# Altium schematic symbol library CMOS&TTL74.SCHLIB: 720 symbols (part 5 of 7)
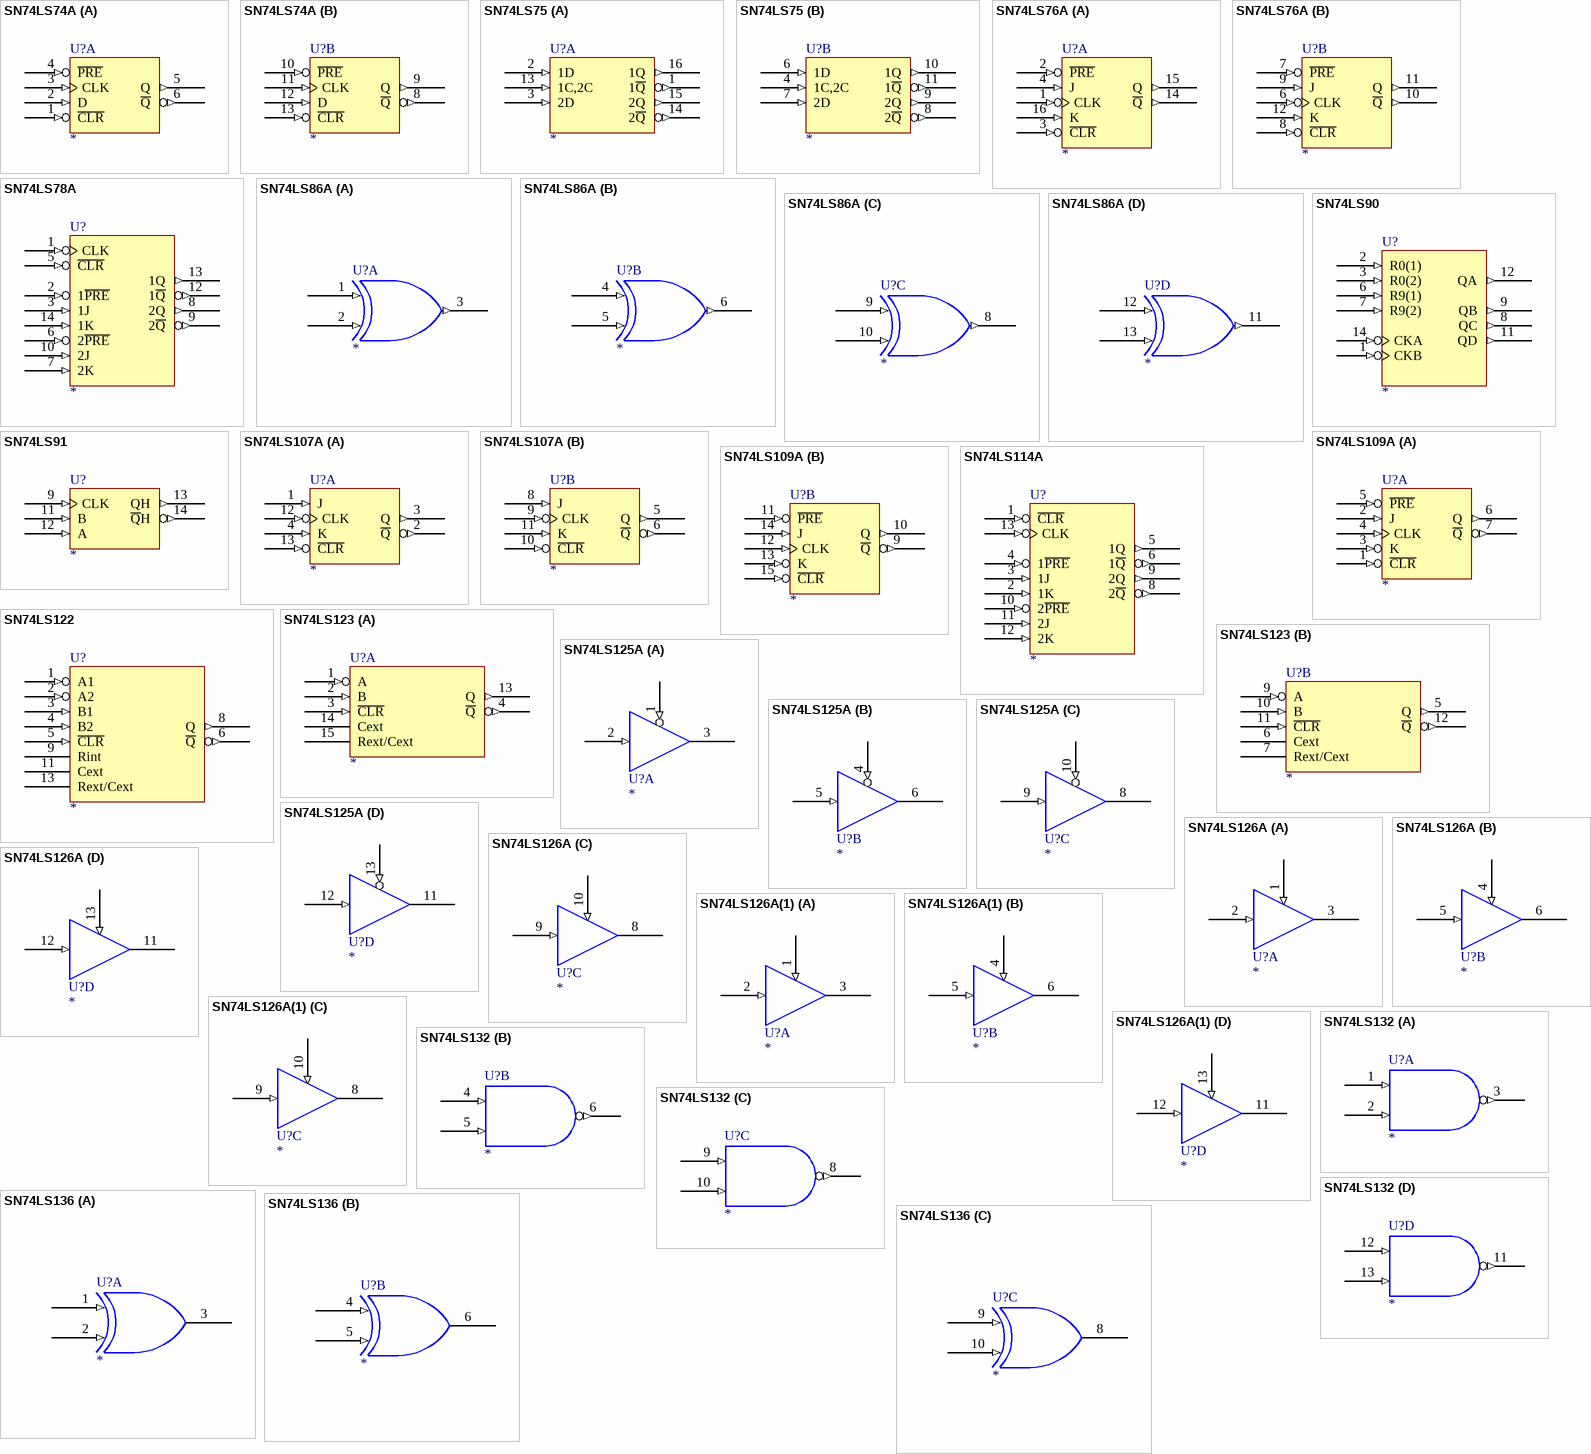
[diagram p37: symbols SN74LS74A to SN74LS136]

## SN74LS86A
designator U?
QUAD 2-IN XOR  G
footprint SO14
footprint DIP-14
part A pins: 1 (in), 2 (in), 3 (out), 7 GND (power) hidden to GND, 14 VCC (power) hidden to VCC
part B pins: 4 (in), 5 (in), 6 (out), 7 GND (power) hidden to GND, 14 VCC (power) hidden to VCC
part C pins: 7 GND (power) hidden to GND, 8 (out), 9 (in), 10 (in), 14 VCC (power) hidden to VCC
part D pins: 7 GND (power) hidden to GND, 11 (out), 12 (in), 13 (in), 14 VCC (power) hidden to VCC
1 alternate drawing of the same symbol

## SN74LS90
designator U?
DECADE DIV-BY-12 BIN CNT
footprint SO14
footprint DIP-14
pins: 1 CKB (in), 2 R0(1) (in), 3 R0(2) (in), 5 VCC (power) hidden to VCC, 6 R9(1) (in), 7 R9(2) (in), 8 QC (out), 9 QB (out), 10 GND (power) hidden to GND, 11 QD (out), 12 QA (out), 14 CKA (in)
1 alternate drawing of the same symbol

## SN74LS91
designator U?
8-BIT SHIFT REG
footprint SO14
footprint DIP-14
pins: 5 VCC (power) hidden to VCC, 9 CLK (in), 10 GND (power) hidden to GND, 11 B (in), 12 A (in), 13 QH (out), 14 ~{Q}H (out)
1 alternate drawing of the same symbol

## SN74LS107A
designator U?
DUAL J-K FF CR
footprint SO14
footprint DIP-14
part A pins: 1 J (in), 2 ~{Q} (out), 3 Q (out), 4 K (in), 7 GND (power) hidden to GND, 12 CLK (in), 13 ~{CLR} (in), 14 VCC (power) hidden to VCC
part B pins: 5 Q (out), 6 ~{Q} (out), 7 GND (power) hidden to GND, 8 J (in), 9 CLK (in), 10 ~{CLR} (in), 11 K (in), 14 VCC (power) hidden to VCC
1 alternate drawing of the same symbol

## SN74LS109A
designator U?
DUAL J-K PET FF RS CR
footprint SO16
footprint DIP-16
part A pins: 1 ~{CLR} (in), 2 J (in), 3 K (in), 4 CLK (in), 5 ~{PRE} (in), 6 Q (out), 7 ~{Q} (out), 8 GND (power) hidden to GND, 16 VCC (power) hidden to VCC
part B pins: 8 GND (power) hidden to GND, 9 ~{Q} (out), 10 Q (out), 11 ~{PRE} (in), 12 CLK (in), 13 K (in), 14 J (in), 15 ~{CLR} (in), 16 VCC (power) hidden to VCC
1 alternate drawing of the same symbol

## SN74LS114A
designator U?
DUAL J-K NET FF RS COM CR COM CLK
footprint SO14
footprint DIP-14
pins: 1 ~{CLR} (in), 2 1K (in), 3 1J (in), 4 1~{PRE} (in), 5 1Q (out), 6 1~{Q} (out), 7 GND (power) hidden to GND, 8 2~{Q} (out), 9 2Q (out), 10 2~{PRE} (in), 11 2J (in), 12 2K (in), 13 CLK (in), 14 VCC (power) hidden to VCC
1 alternate drawing of the same symbol

## SN74LS122
designator U?
RETRIGGERABLE MONOSTABLE MULTIVIBRATOR
footprint SO14
footprint DIP-14
pins: 1 A1 (in), 2 A2 (in), 3 B1 (in), 4 B2 (in), 5 ~{CLR} (in), 6 ~{Q} (out), 7 GND (power) hidden to GND, 8 Q (out), 9 Rint, 11 Cext, 13 Rext/Cext, 14 VCC (power) hidden to VCC
1 alternate drawing of the same symbol

## SN74LS123
designator U?
RETRIGGERABLE MONOSTABLE MULTIVIBRATOR
footprint SO16
footprint DIP-16
part A pins: 1 A (in), 2 B (in), 3 ~{CLR} (in), 4 ~{Q} (out), 8 GND (power) hidden to GND, 13 Q (out), 14 Cext, 15 Rext/Cext, 16 VCC (power) hidden to VCC
part B pins: 5 Q (out), 6 Cext, 7 Rext/Cext, 8 GND (power) hidden to GND, 9 A (in), 10 B (in), 11 ~{CLR} (in), 12 ~{Q} (out), 16 VCC (power) hidden to VCC
1 alternate drawing of the same symbol

## SN74LS125A
designator U?
QUAD BUS BUF 3SO
footprint SO14
footprint DIP-14
part A pins: 1 (in), 2 (in), 3 (hiz), 7 GND (power) hidden to GND, 14 VCC (power) hidden to VCC
part B pins: 4 (in), 5 (in), 6 (hiz), 7 GND (power) hidden to GND, 14 VCC (power) hidden to VCC
part C pins: 7 GND (power) hidden to GND, 8 (hiz), 9 (in), 10 (in), 14 VCC (power) hidden to VCC
part D pins: 7 GND (power) hidden to GND, 11 (hiz), 12 (in), 13 (in), 14 VCC (power) hidden to VCC
2 alternate drawings of the same symbol

## SN74LS126A
designator U?
QUAD BUS BUF 3SO
footprint SO14
footprint DIP-14
part A pins: 1 (in), 2 (in), 3 (hiz), 7 GND (power) hidden to GND, 14 VCC (power) hidden to VCC
part B pins: 4 (in), 5 (in), 6 (hiz), 7 GND (power) hidden to GND, 14 VCC (power) hidden to VCC
part C pins: 7 GND (power) hidden to GND, 8 (hiz), 9 (in), 10 (in), 14 VCC (power) hidden to VCC
part D pins: 7 GND (power) hidden to GND, 11 (hiz), 12 (in), 13 (in), 14 VCC (power) hidden to VCC
2 alternate drawings of the same symbol

## SN74LS126A(1)
designator U?
QUAD BUS BUF 3SO
footprint DIP-14
part A pins: 1 (in), 2 (in), 3 (hiz), 7 GND (power) hidden to GND, 14 VCC (power) hidden to VCC
part B pins: 4 (in), 5 (in), 6 (hiz), 7 GND (power) hidden to GND, 14 VCC (power) hidden to VCC
part C pins: 7 GND (power) hidden to GND, 8 (hiz), 9 (in), 10 (in), 14 VCC (power) hidden to VCC
part D pins: 7 GND (power) hidden to GND, 11 (hiz), 12 (in), 13 (in), 14 VCC (power) hidden to VCC
2 alternate drawings of the same symbol

## SN74LS132
designator U?
QUAD 2-IN POS NAND SCH
footprint SO14
footprint DIP-14
part A pins: 1 (in), 2 (in), 3 (out), 7 GND (power) hidden to GND, 14 VCC (power) hidden to VCC
part B pins: 4 (in), 5 (in), 6 (out), 7 GND (power) hidden to GND, 14 VCC (power) hidden to VCC
part C pins: 7 GND (power) hidden to GND, 8 (out), 9 (in), 10 (in), 14 VCC (power) hidden to VCC
part D pins: 7 GND (power) hidden to GND, 11 (out), 12 (in), 13 (in), 14 VCC (power) hidden to VCC
2 alternate drawings of the same symbol

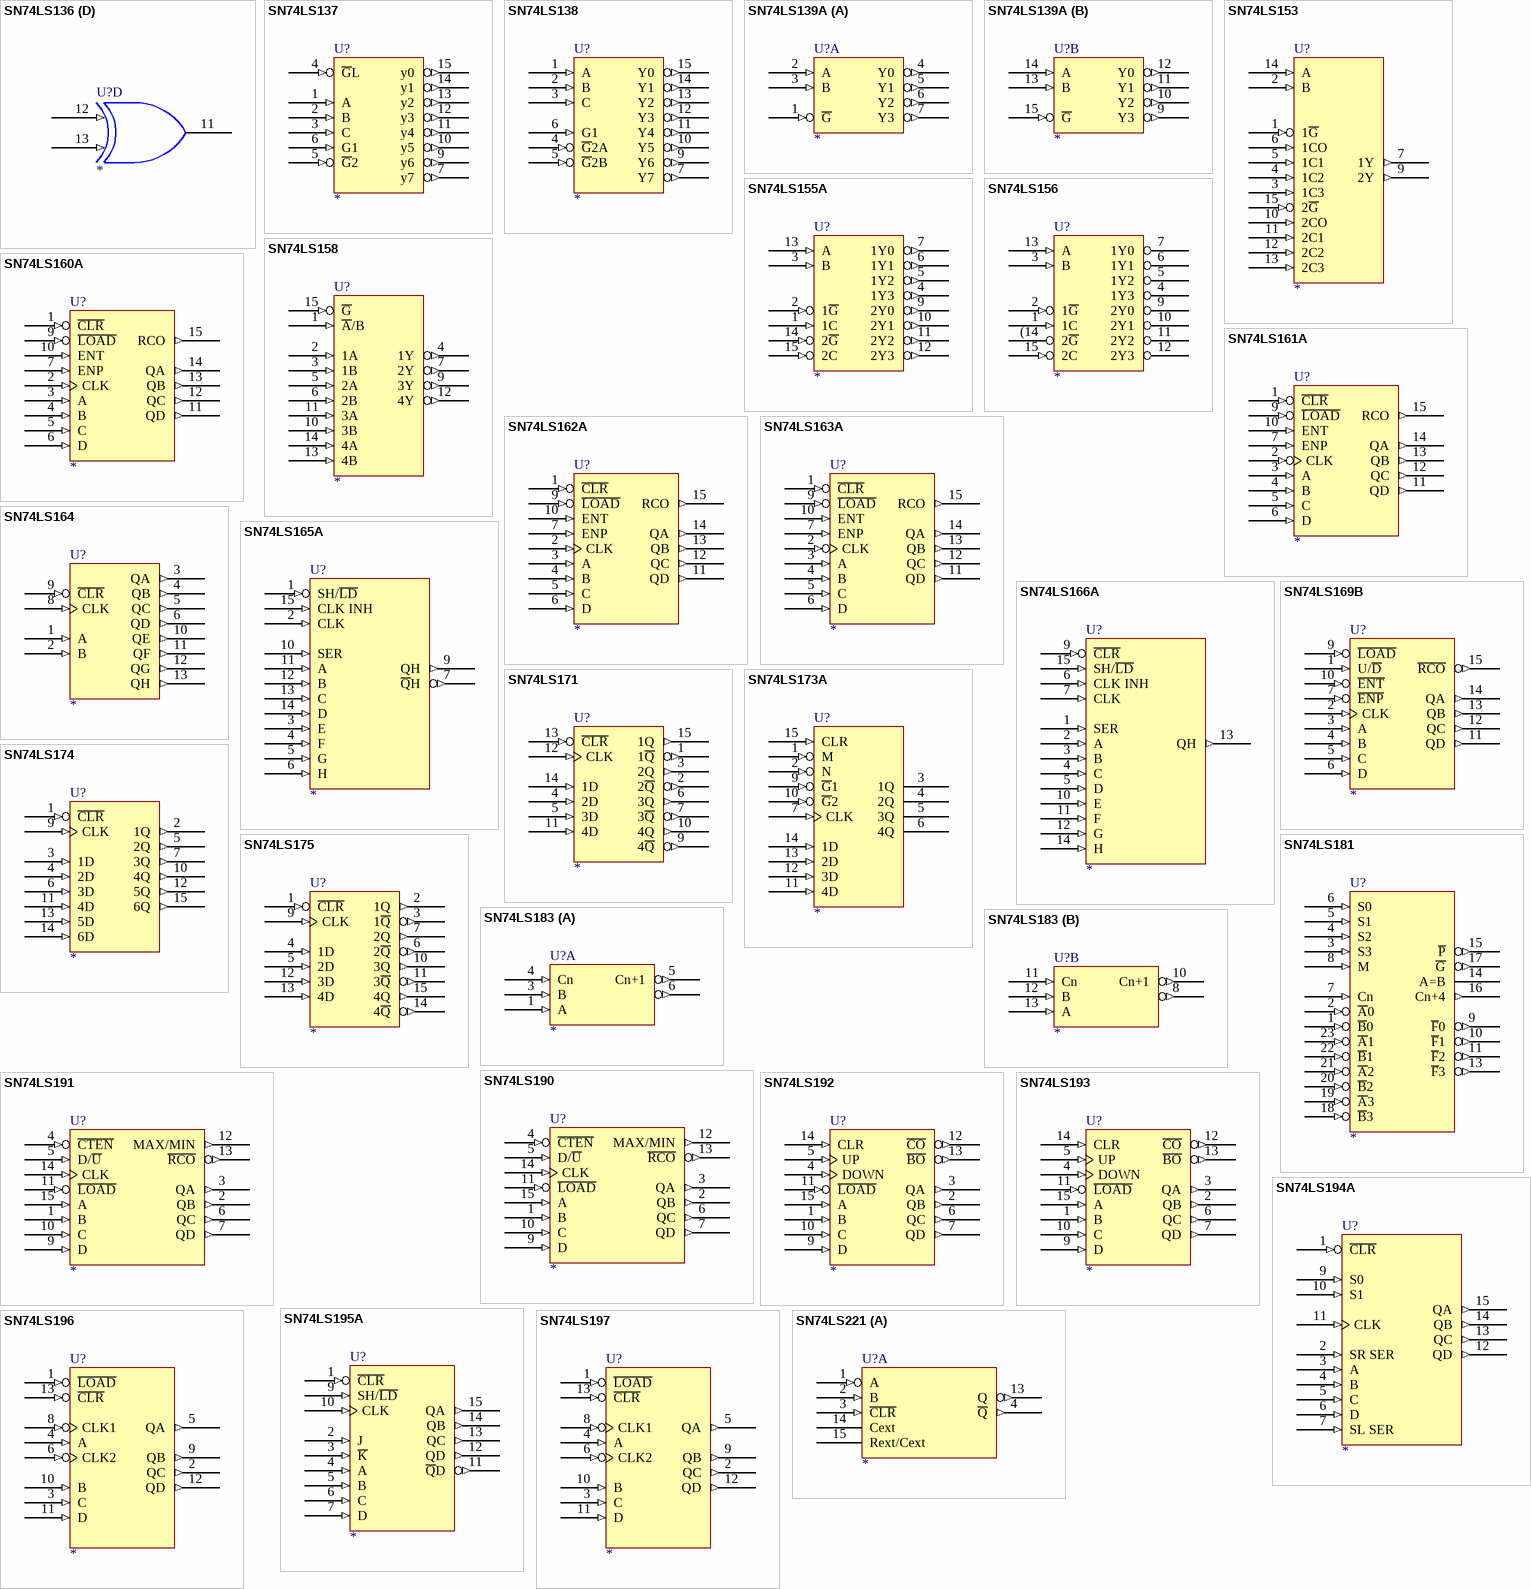
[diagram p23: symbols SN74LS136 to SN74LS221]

## SN74LS136
designator U?
QUAD 2-IN XOR  G OCO
footprint DIP-14
part A pins: 1 (in), 2 (in), 3 (oc), 7 GND (power) hidden to GND, 14 VCC (power) hidden to VCC
part B pins: 4 (in), 5 (in), 6 (oc), 7 GND (power) hidden to GND, 14 VCC (power) hidden to VCC
part C pins: 7 GND (power) hidden to GND, 8 (oc), 9 (in), 10 (in), 14 VCC (power) hidden to VCC
part D pins: 7 GND (power) hidden to GND, 11 (oc), 12 (in), 13 (in), 14 VCC (power) hidden to VCC
1 alternate drawing of the same symbol

## SN74LS137
designator U?
3-8LINE DEC/DEMUL ADDRESS LCH
footprint SO16
footprint DIP-16
pins: 1 A (in), 2 B (in), 3 C (in), 4 ~{G}L (in), 5 ~{G}2 (in), 6 G1 (in), 7 y7 (out), 8 GND (power) hidden to GND, 9 y6 (out), 10 y5 (out), 11 y4 (out), 12 y3 (out), 13 y2 (out), 14 y1 (out), 15 y0 (out), 16 VCC (power) hidden to VCC
1 alternate drawing of the same symbol

## SN74LS138
designator U?
3-8LINE DEC/DEMUL
footprint SO16
footprint DIP-16
pins: 1 A (in), 2 B (in), 3 C (in), 4 ~{G}2A (in), 5 ~{G}2B (in), 6 G1 (in), 7 Y7 (out), 8 GND (power) hidden to GND, 9 Y6 (out), 10 Y5 (out), 11 Y4 (out), 12 Y3 (out), 13 Y2 (out), 14 Y1 (out), 15 Y0 (out), 16 VCC (power) hidden to VCC
1 alternate drawing of the same symbol

## SN74LS139A
designator U?
DUAL 2-4LINE DEC/DEMULT
footprint SO16
footprint DIP-16
part A pins: 1 ~{G} (in), 2 A (in), 3 B (in), 4 Y0 (out), 5 Y1 (out), 6 Y2 (out), 7 Y3 (out), 8 GND (power) hidden to GND, 16 VCC (power) hidden to VCC
part B pins: 8 GND (power) hidden to GND, 9 Y3 (out), 10 Y2 (out), 11 Y1 (out), 12 Y0 (out), 13 B (in), 14 A (in), 15 ~{G} (in), 16 VCC (power) hidden to VCC
1 alternate drawing of the same symbol

## SN74LS153
designator U?
DUAL 4-1 LINE DATA SELEC/MUX
footprint SO16
footprint DIP-16
pins: 1 1~{G} (in), 2 B (in), 3 1C3 (in), 4 1C2 (in), 5 1C1 (in), 6 1CO (in), 7 1Y (out), 8 GND (power) hidden to GND, 9 2Y (out), 10 2CO (in), 11 2C1 (in), 12 2C2 (in), 13 2C3 (in), 14 A (in), 15 2~{G} (in), 16 VCC (power) hidden to VCC
1 alternate drawing of the same symbol

## SN74LS155A
designator U?
DUAL 2-4 LINE DEC/DEMUL
footprint SO16
footprint DIP-16
pins: 1 1C (in), 2 1~{G} (in), 3 B (in), 4 1Y3 (out), 5 1Y2 (out), 6 1Y1 (out), 7 1Y0 (out), 8 GND (power) hidden to GND, 9 2Y0 (out), 10 2Y1 (out), 11 2Y2 (out), 12 2Y3 (out), 13 A (in), 14 2~{G} (in), 15 2C (in), 16 VCC (power) hidden to VCC
1 alternate drawing of the same symbol

## SN74LS156
designator U?
DUAL 2-4 LINE DEC/DEMUL
footprint DIP-16
pins: 1 1C (in), 2 1~{G} (in), 3 B (in), 4 1Y3 (oc), 5 1Y2 (oc), 6 1Y1 (oc), 7 1Y0 (oc), 8 GND (power) hidden to GND, 9 2Y0 (oc), 10 2Y1 (oc), 11 2Y2 (oc), 12 2Y3 (oc), 13 A (in), 15 2C (in), 16 VCC (power) hidden to VCC, (14 2~{G}
1 alternate drawing of the same symbol

## SN74LS158
designator U?
QUAD 2-1LINE DATA SELEC/MUX
footprint SO16
footprint DIP-16
pins: 1 ~{A}/B (in), 2 1A (in), 3 1B (in), 4 1Y (out), 5 2A (in), 6 2B (in), 7 2Y (out), 8 GND (power) hidden to GND, 9 3Y (out), 10 3B (in), 11 3A (in), 12 4Y (out), 13 4B (in), 14 4A (in), 15 ~{G} (in), 16 VCC (power) hidden to VCC
1 alternate drawing of the same symbol

## SN74LS160A
designator U?
SYN 4-BIT CNT
footprint SO16
footprint DIP-16
pins: 1 ~{CLR} (in), 2 CLK (in), 3 A (in), 4 B (in), 5 C (in), 6 D (in), 7 ENP (in), 8 GND (power) hidden to GND, 9 ~{LOAD} (in), 10 ENT (in), 11 QD (out), 12 QC (out), 13 QB (out), 14 QA (out), 15 RCO (out), 16 VCC (power) hidden to VCC
1 alternate drawing of the same symbol

## SN74LS161A
designator U?
SYN 4-BIT CNT
footprint DIP-16
footprint SO16
pins: 1 ~{CLR} (in), 2 CLK (in), 3 A (in), 4 B (in), 5 C (in), 6 D (in), 7 ENP (in), 8 GND (power) hidden to GND, 9 ~{LOAD} (in), 10 ENT (in), 11 QD (out), 12 QC (out), 13 QB (out), 14 QA (out), 15 RCO (out), 16 VCC (power) hidden to VCC
1 alternate drawing of the same symbol

## SN74LS162A
designator U?
SYN 4-BIT CNT
footprint SO16
footprint DIP-16
pins: 1 ~{CLR} (in), 2 CLK (in), 3 A (in), 4 B (in), 5 C (in), 6 D (in), 7 ENP (in), 8 GND (power) hidden to GND, 9 ~{LOAD} (in), 10 ENT (in), 11 QD (out), 12 QC (out), 13 QB (out), 14 QA (out), 15 RCO (out), 16 VCC (power) hidden to VCC
1 alternate drawing of the same symbol

## SN74LS163A
designator U?
SYN 4-BIT CNT
footprint SO16
footprint DIP-16
pins: 1 ~{CLR} (in), 2 CLK (in), 3 A (in), 4 B (in), 5 C (in), 6 D (in), 7 ENP (in), 8 GND (power) hidden to GND, 9 ~{LOAD} (in), 10 ENT (in), 11 QD (out), 12 QC (out), 13 QB (out), 14 QA (out), 15 RCO (out), 16 VCC (power) hidden to VCC
1 alternate drawing of the same symbol

## SN74LS164
designator U?
8-BIT PALL SERI SFT REG
footprint SO14
footprint DIP-14
pins: 1 A (in), 2 B (in), 3 QA (out), 4 QB (out), 5 QC (out), 6 QD (out), 7 GND (power) hidden to GND, 8 CLK (in), 9 ~{CLR} (in), 10 QE (out), 11 QF (out), 12 QG (out), 13 QH (out), 14 VCC (power) hidden to VCC
1 alternate drawing of the same symbol

## SN74LS165A
designator U?
PALL LOAD 8-BIT SFT REG
footprint SO16
footprint DIP-16
pins: 1 SH/~{LD} (in), 2 CLK (in), 3 E (in), 4 F (in), 5 G (in), 6 H (in), 7 ~{Q}H (out), 8 GND (power) hidden to GND, 9 QH (out), 10 SER (in), 11 A (in), 12 B (in), 13 C (in), 14 D (in), 15 CLK INH (in), 16 VCC (power) hidden to VCC
1 alternate drawing of the same symbol

## SN74LS166A
designator U?
PALL LOAD 8-BIT SFT REG
footprint DIP-16
footprint SO16
pins: 1 SER (in), 2 A (in), 3 B (in), 4 C (in), 5 D (in), 6 CLK INH (in), 7 CLK (in), 8 GND (power) hidden to GND, 9 ~{CLR} (in), 10 E (in), 11 F (in), 12 G (in), 13 QH (out), 14 H (in), 15 SH/~{LD} (in), 16 VCC (power) hidden to VCC
1 alternate drawing of the same symbol

## SN74LS169B
designator U?
SYN 4-BIT UP/DOWN BIN CNT
footprint SO16
footprint DIP-16
pins: 1 U/~{D} (in), 2 CLK (in), 3 A (in), 4 B (in), 5 C (in), 6 D (in), 7 ~{ENP} (in), 8 GND (power) hidden to GND, 9 ~{LOAD} (in), 10 ~{ENT} (in), 11 QD (out), 12 QC (out), 13 QB (out), 14 QA (out), 15 ~{RCO} (out), 16 VCC (power) hidden to VCC
1 alternate drawing of the same symbol

## SN74LS171
designator U?
QUAD D-TYPE FF CR
footprint SO16
footprint DIP-16
pins: 1 1~{Q} (out), 2 2~{Q} (out), 3 2Q (out), 4 2D (in), 5 3D (in), 6 3Q (out), 7 3~{Q} (out), 8 GND (power) hidden to GND, 9 4~{Q} (out), 10 4Q (out), 11 4D (in), 12 CLK (in), 13 ~{CLR} (in), 14 1D (in), 15 1Q (out), 16 VCC (power) hidden to VCC
1 alternate drawing of the same symbol

## SN74LS173A
designator U?
4-BIT D-TYPE REG 3SO
footprint SO16
footprint DIP-16
pins: 1 M (in), 2 N (in), 3 1Q (hiz), 4 2Q (hiz), 5 3Q (hiz), 6 4Q (hiz), 7 CLK (in), 8 GND (power) hidden to GND, 9 ~{G}1 (in), 10 ~{G}2 (in), 11 4D (in), 12 3D (in), 13 2D (in), 14 1D (in), 15 CLR (in), 16 VCC (power) hidden to VCC
1 alternate drawing of the same symbol

## SN74LS174
designator U?
HEX D-TYPE FF CR
footprint SO16
footprint DIP-16
pins: 1 ~{CLR} (in), 2 1Q (out), 3 1D (in), 4 2D (in), 5 2Q (out), 6 3D (in), 7 3Q (out), 8 GND (power) hidden to GND, 9 CLK (in), 10 4Q (out), 11 4D (in), 12 5Q (out), 13 5D (in), 14 6D (in), 15 6Q (out), 16 VCC (power) hidden to VCC
1 alternate drawing of the same symbol

## SN74LS175
designator U?
QUAD D-TYPE FF CR
footprint SO16
footprint DIP-16
pins: 1 ~{CLR} (in), 2 1Q (out), 3 1~{Q} (out), 4 1D (in), 5 2D (in), 6 2~{Q} (out), 7 2Q (out), 8 GND (power) hidden to GND, 9 CLK (in), 10 3Q (out), 11 3~{Q} (out), 12 3D (in), 13 4D (in), 14 4~{Q} (out), 15 4Q (out), 16 VCC (power) hidden to VCC
1 alternate drawing of the same symbol

## SN74LS181
designator U?
ALU/FN GNR
footprint SO24W
footprint DIP-24
pins: 1 ~{B}0 (in), 2 ~{A}0 (in), 3 S3 (in), 4 S2 (in), 5 S1 (in), 6 S0 (in), 7 Cn (in), 8 M (in), 9 ~{F}0 (out), 10 ~{F}1 (out), 11 ~{F}2 (out), 12 GND (power) hidden to GND, 13 ~{F}3 (out), 14 A=B (oc), 15 ~{P} (out), 16 Cn+4 (out), 17 ~{G} (out), 18 ~{B}3 (in), 19 ~{A}3 (in), 20 ~{B}2 (in), 21 ~{A}2 (in), 22 ~{B}1 (in), 23 ~{A}1 (in), 24 VCC (power) hidden to VCC
1 alternate drawing of the same symbol

## SN74LS183
designator U?
DUAL CARRY-SAVE FULL ADD
footprint DIP-14
part A pins: 1 A (in), 3 B (in), 4 Cn (in), 5 Cn+1 (out), 6 (out), 7 GND (power) hidden to GND, 14 VCC (power) hidden to VCC
part B pins: 7 GND (power) hidden to GND, 8 (out), 10 Cn+1 (out), 11 Cn (in), 12 B (in), 13 A (in), 14 VCC (power) hidden to VCC
1 alternate drawing of the same symbol

## SN74LS190
designator U?
SYN UP/DOWN CNT DOWN/UP MODE CONTTOL
footprint DIP-16
footprint SO16
pins: 1 B (in), 2 QB (out), 3 QA (out), 4 ~{CTEN} (in), 5 D/~{U} (in), 6 QC (out), 7 QD (out), 8 GND (power) hidden to GND, 9 D (in), 10 C (in), 11 ~{LOAD} (in), 12 MAX/MIN (out), 13 ~{RCO} (out), 14 CLK (in), 15 A (in), 16 VCC (power) hidden to VCC
1 alternate drawing of the same symbol

## SN74LS191
designator U?
SYN UP/DOWN CNT DOWN/UP MODE CONTTOL
footprint SO16
footprint DIP-16
pins: 1 B (in), 2 QB (out), 3 QA (out), 4 ~{CTEN} (in), 5 D/~{U} (in), 6 QC (out), 7 QD (out), 8 GND (power) hidden to GND, 9 D (in), 10 C (in), 11 ~{LOAD} (in), 12 MAX/MIN (out), 13 ~{RCO} (out), 14 CLK (in), 15 A (in), 16 VCC (power) hidden to VCC
1 alternate drawing of the same symbol

## SN74LS192
designator U?
SYN 4-BIT UP/DOWN CNT DUAL CLK CR
footprint SO16
footprint DIP-16
pins: 1 B (in), 2 QB (out), 3 QA (out), 4 DOWN (in), 5 UP (in), 6 QC (out), 7 QD (out), 8 GND (power) hidden to GND, 9 D (in), 10 C (in), 11 ~{LOAD} (in), 12 ~{CO} (out), 13 ~{BO} (out), 14 CLR (in), 15 A (in), 16 VCC (power) hidden to VCC
1 alternate drawing of the same symbol

## SN74LS193
designator U?
SYN 4-BIT UP/DOWN CNT DUAL CLK CR
footprint DIP-16
footprint SO16
pins: 1 B (in), 2 QB (out), 3 QA (out), 4 DOWN (in), 5 UP (in), 6 QC (out), 7 QD (out), 8 GND (power) hidden to GND, 9 D (in), 10 C (in), 11 ~{LOAD} (in), 12 ~{CO} (out), 13 ~{BO} (out), 14 CLR (in), 15 A (in), 16 VCC (power) hidden to VCC
1 alternate drawing of the same symbol

## SN74LS194A
designator U?
4-BIT BIDIRECTIONAL UNIVERSAL SFT REG
footprint SO16
footprint DIP-16
pins: 1 ~{CLR} (in), 2 SR SER (in), 3 A (in), 4 B (in), 5 C (in), 6 D (in), 7 SL SER (in), 8 GND (power) hidden to GND, 9 S0 (in), 10 S1 (in), 11 CLK (in), 12 QD (out), 13 QC (out), 14 QB (out), 15 QA (out), 16 VCC (power) hidden to VCC
1 alternate drawing of the same symbol

## SN74LS195A
designator U?
4-BIT PARALLEL ACCESS SFT REG
footprint SO16
footprint DIP-16
pins: 1 ~{CLR} (in), 2 J (in), 3 ~{K} (in), 4 A (in), 5 B (in), 6 C (in), 7 D (in), 8 GND (power) hidden to GND, 9 SH/~{LD} (in), 10 CLK (in), 11 ~{Q}D (out), 12 QD (out), 13 QC (out), 14 QB (out), 15 QA (out), 16 VCC (power) hidden to VCC
1 alternate drawing of the same symbol

## SN74LS196
designator U?
50/30/100-MHZ PRESETTABLE DECADE BIN CNT LCH
footprint DIP-16
footprint SO16
pins: 1 ~{LOAD} (in), 2 QC (out), 3 C (in), 4 A (in), 5 QA (out), 6 CLK2 (in), 7 GND (power) hidden to GND, 8 CLK1 (in), 9 QB (out), 10 B (in), 11 D (in), 12 QD (out), 13 ~{CLR} (in), 14 VCC (power) hidden to VCC
1 alternate drawing of the same symbol

## SN74LS197
designator U?
50/30/100-MHZ PRESETTABLE DECADE BIN CNT LCH
footprint SO16
footprint DIP-16
pins: 1 ~{LOAD} (in), 2 QC (out), 3 C (in), 4 A (in), 5 QA (out), 6 CLK2 (in), 7 GND (power) hidden to GND, 8 CLK1 (in), 9 QB (out), 10 B (in), 11 D (in), 12 QD (out), 13 ~{CLR} (in), 14 VCC (power) hidden to VCC
1 alternate drawing of the same symbol

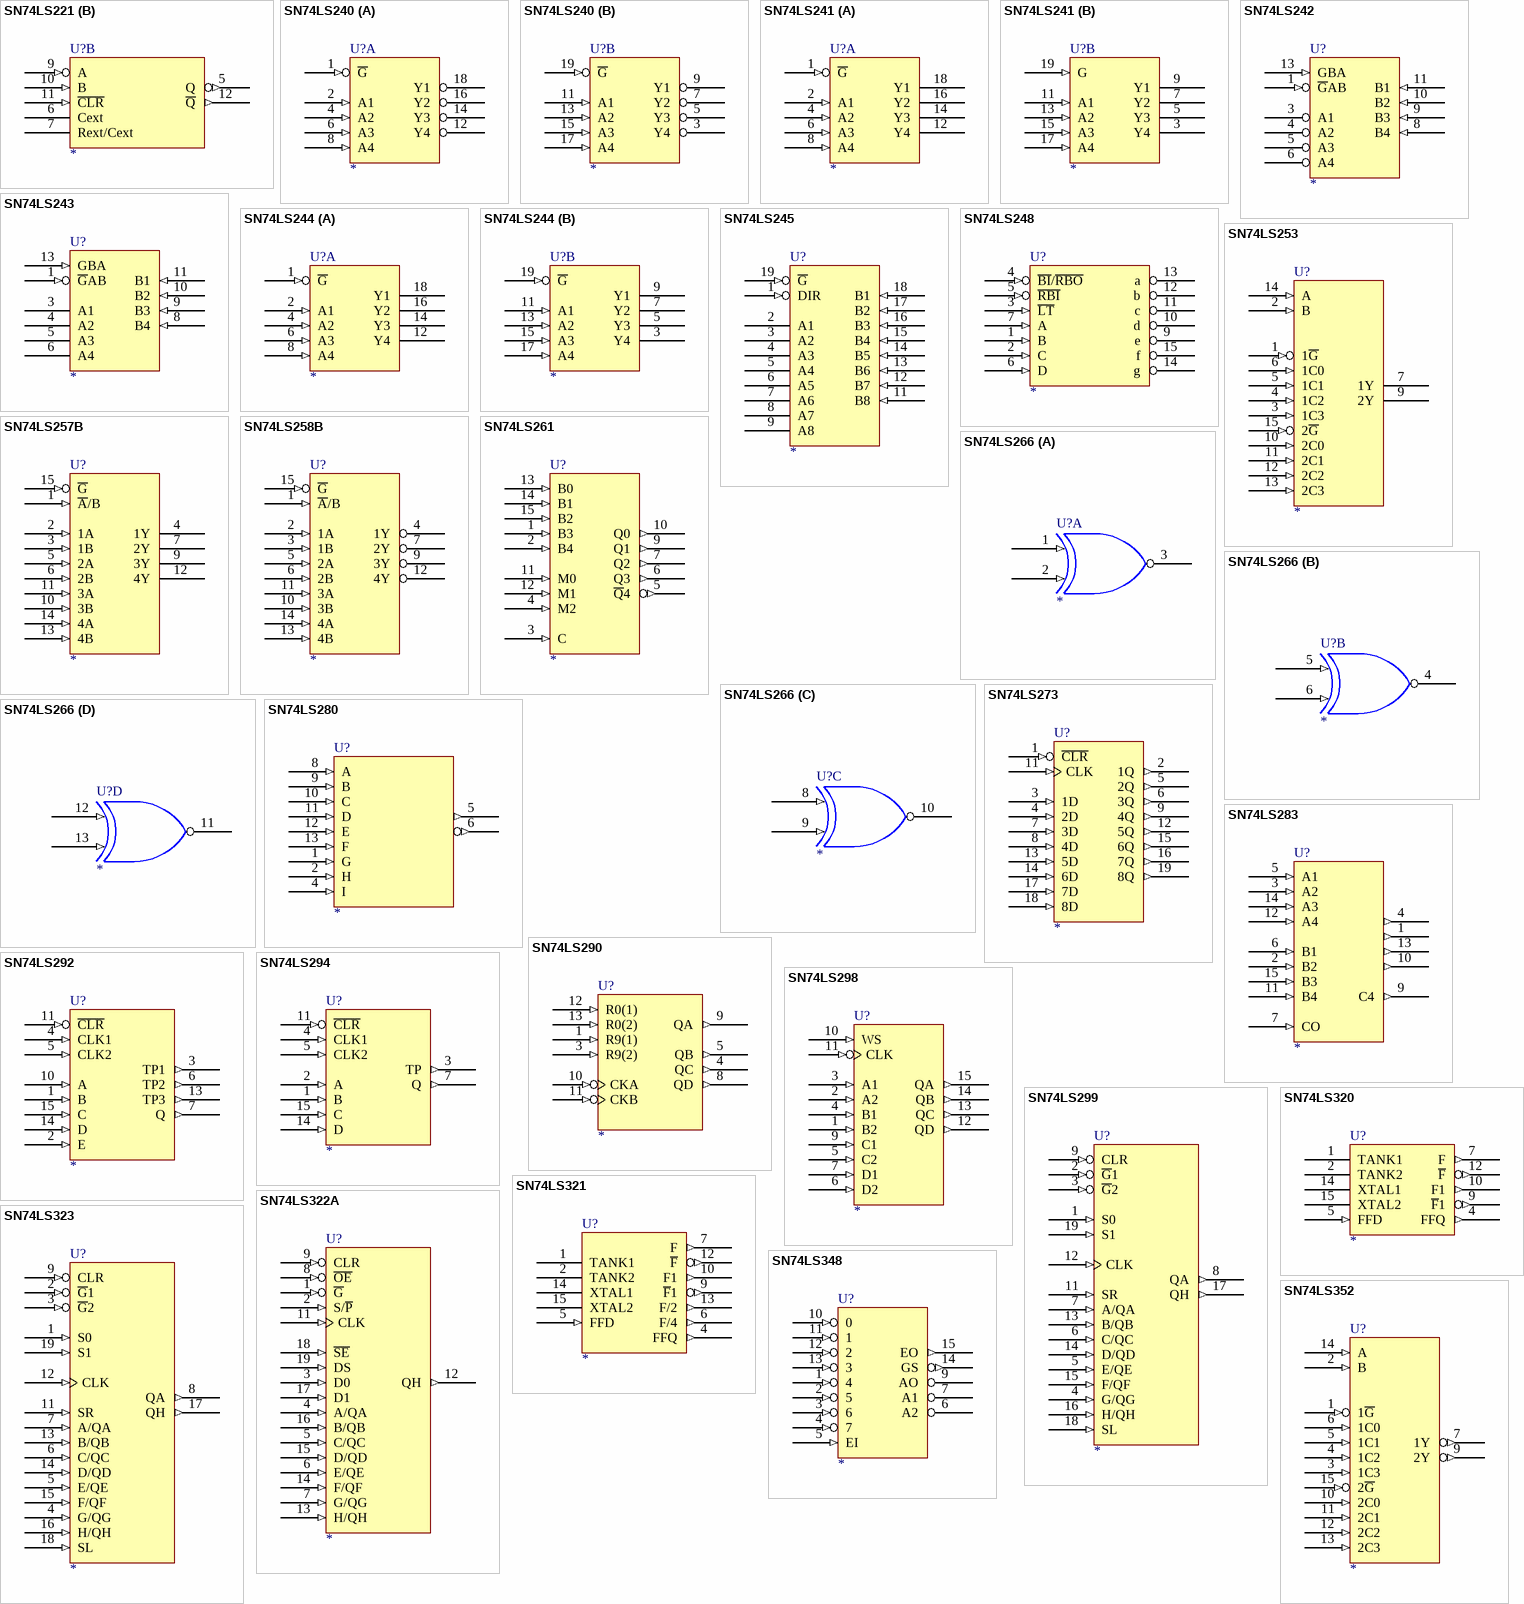
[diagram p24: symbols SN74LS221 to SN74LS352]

## SN74LS221
designator U?
DUAL MONOSTABLE MULTIVIBRATOR SCHI
footprint SO16
footprint DIP-16
part A pins: 1 A (in), 2 B (in), 3 ~{CLR} (in), 4 ~{Q} (out), 8 GND (power) hidden to GND, 13 Q (out), 14 Cext, 15 Rext/Cext, 16 VCC (power) hidden to VCC
part B pins: 5 Q (out), 6 Cext, 7 Rext/Cext, 8 GND (power) hidden to GND, 9 A (in), 10 B (in), 11 ~{CLR} (in), 12 ~{Q} (out), 16 VCC (power) hidden to VCC
1 alternate drawing of the same symbol

## SN74LS240
designator U?
OCTAL BUF AND LIN DRV 3SO
footprint SO20W
footprint DIP-20
part A pins: 1 ~{G} (in), 2 A1 (in), 4 A2 (in), 6 A3 (in), 8 A4 (in), 10 GND (power) hidden to GND, 12 Y4 (hiz), 14 Y3 (hiz), 16 Y2 (hiz), 18 Y1 (hiz), 20 VCC (power) hidden to VCC
part B pins: 3 Y4 (hiz), 5 Y3 (hiz), 7 Y2 (hiz), 9 Y1 (hiz), 10 GND (power) hidden to GND, 11 A1 (in), 13 A2 (in), 15 A3 (in), 17 A4 (in), 19 ~{G} (in), 20 VCC (power) hidden to VCC
1 alternate drawing of the same symbol

## SN74LS241
designator U?
OCTAL BUF AND LIN DRV 3SO
footprint SO20W
footprint DIP-20
part A pins: 1 ~{G} (in), 2 A1 (in), 4 A2 (in), 6 A3 (in), 8 A4 (in), 10 GND (power) hidden to GND, 12 Y4 (hiz), 14 Y3 (hiz), 16 Y2 (hiz), 18 Y1 (hiz), 20 VCC (power) hidden to VCC
part B pins: 3 Y4 (hiz), 5 Y3 (hiz), 7 Y2 (hiz), 9 Y1 (hiz), 10 GND (power) hidden to GND, 11 A1 (in), 13 A2 (in), 15 A3 (in), 17 A4 (in), 19 G (in), 20 VCC (power) hidden to VCC
1 alternate drawing of the same symbol

## SN74LS242
designator U?
QUAD BUS TRANSCEIVER
footprint SO14
footprint DIP-14
pins: 1 ~{G}AB (in), 3 A1 (hiz), 4 A2 (hiz), 5 A3 (hiz), 6 A4 (hiz), 7 GND (power) hidden to GND, 8 B4 (in), 9 B3 (in), 10 B2 (in), 11 B1 (in), 13 GBA (in), 14 VCC (power) hidden to VCC
1 alternate drawing of the same symbol

## SN74LS243
designator U?
QUAD BUS TRANSCEIVER
footprint SO14
footprint DIP-14
pins: 1 ~{G}AB (in), 3 A1 (hiz), 4 A2 (hiz), 5 A3 (hiz), 6 A4 (hiz), 7 GND (power) hidden to GND, 8 B4 (in), 9 B3 (in), 10 B2 (in), 11 B1 (in), 13 GBA (in), 14 VCC (power) hidden to VCC
1 alternate drawing of the same symbol

## SN74LS244
designator U?
OCTAL BUF AND LIN DRV 3SO
footprint DIP-20
footprint SO20W
part A pins: 1 ~{G} (in), 2 A1 (in), 4 A2 (in), 6 A3 (in), 8 A4 (in), 10 GND (power) hidden to GND, 12 Y4 (hiz), 14 Y3 (hiz), 16 Y2 (hiz), 18 Y1 (hiz), 20 VCC (power) hidden to VCC
part B pins: 3 Y4 (hiz), 5 Y3 (hiz), 7 Y2 (hiz), 9 Y1 (hiz), 10 GND (power) hidden to GND, 11 A1 (in), 13 A2 (in), 15 A3 (in), 17 A4 (in), 19 ~{G} (in), 20 VCC (power) hidden to VCC
1 alternate drawing of the same symbol

## SN74LS245
designator U?
QUAD BUS TRANSCEIVER 3SO
footprint SO20W
footprint DIP-20
pins: 1 DIR (in), 2 A1 (hiz), 3 A2 (hiz), 4 A3 (hiz), 5 A4 (hiz), 6 A5 (hiz), 7 A6 (hiz), 8 A7 (hiz), 9 A8 (hiz), 10 GND (power) hidden to GND, 11 B8 (in), 12 B7 (in), 13 B6 (in), 14 B5 (in), 15 B4 (in), 16 B3 (in), 17 B2 (in), 18 B1 (in), 19 ~{G} (in), 20 VCC (power) hidden to VCC
1 alternate drawing of the same symbol

## SN74LS248
designator U?
BCD-TO-SEVEN-SEGMENTDEC/DRV
footprint DIP-16
footprint SO16
pins: 1 B (in), 2 C (in), 3 ~{LT} (in), 4 ~{BI}/~{RBO} (in), 5 ~{RBI} (in), 6 D (in), 7 A (in), 8 GND (power) hidden to GND, 9 e (oc), 10 d (oc), 11 c (oc), 12 b (oc), 13 a (oc), 14 g (oc), 15 f (oc), 16 VCC (power) hidden to VCC
1 alternate drawing of the same symbol

## SN74LS253
designator U?
DUAL 4-1LINES DATA SLCR/MUX
footprint SO16
footprint DIP-16
pins: 1 1~{G} (in), 2 B (in), 3 1C3 (in), 4 1C2 (in), 5 1C1 (in), 6 1C0 (in), 7 1Y (hiz), 8 GND (power) hidden to GND, 9 2Y (hiz), 10 2C0 (in), 11 2C1 (in), 12 2C2 (in), 13 2C3 (in), 14 A (in), 15 2~{G} (in), 16 VCC (power) hidden to VCC
1 alternate drawing of the same symbol

## SN74LS257B
designator U?
QUAD 2-1LINE DATA SLCR/MUX
footprint SO16
pins: 1 ~{A}/B (in), 2 1A (in), 3 1B (in), 4 1Y (hiz), 5 2A (in), 6 2B (in), 7 2Y (hiz), 8 GND (power) hidden to GND, 9 3Y (hiz), 10 3B (in), 11 3A (in), 12 4Y (hiz), 13 4B (in), 14 4A (in), 15 ~{G} (in), 16 VCC (power) hidden to VCC
1 alternate drawing of the same symbol

## SN74LS258B
designator U?
QUAD 2-1LINE DATA SLCR/MUX
footprint DIP-16
footprint SO16
pins: 1 ~{A}/B (in), 2 1A (in), 3 1B (in), 4 1Y (hiz), 5 2A (in), 6 2B (in), 7 2Y (hiz), 8 GND (power) hidden to GND, 9 3Y (hiz), 10 3B (in), 11 3A (in), 12 4Y (hiz), 13 4B (in), 14 4A (in), 15 ~{G} (in), 16 VCC (power) hidden to VCC
1 alternate drawing of the same symbol

## SN74LS261
designator U?
2-BIT 4-BIT PARALLEL BIN MULT
footprint DIP-16
footprint SO16
pins: 1 B3 (in), 2 B4 (in), 3 C (in), 4 M2 (in), 5 ~{Q}4 (out), 6 Q3 (out), 7 Q2 (out), 8 GND (power) hidden to GND, 9 Q1 (out), 10 Q0 (out), 11 M0 (in), 12 M1 (in), 13 B0 (in), 14 B1 (in), 15 B2 (in), 16 VCC (power) hidden to VCC
1 alternate drawing of the same symbol

## SN74LS266
designator U?
QUAD 2-IN XOR  G OCO
footprint SO14
footprint DIP-14
part A pins: 1 (in), 2 (in), 3 (oc), 7 GND (power) hidden to GND, 14 VCC (power) hidden to VCC
part B pins: 4 (oc), 5 (in), 6 (in), 7 GND (power) hidden to GND, 14 VCC (power) hidden to VCC
part C pins: 7 GND (power) hidden to GND, 8 (in), 9 (in), 10 (oc), 14 VCC (power) hidden to VCC
part D pins: 7 GND (power) hidden to GND, 11 (oc), 12 (in), 13 (in), 14 VCC (power) hidden to VCC
1 alternate drawing of the same symbol

## SN74LS273
designator U?
OCTAL D-TYPE FF CR
footprint DIP-20
footprint SO20W
pins: 1 ~{CLR} (in), 2 1Q (out), 3 1D (in), 4 2D (in), 5 2Q (out), 6 3Q (out), 7 3D (in), 8 4D (in), 9 4Q (out), 10 GND (power) hidden to GND, 11 CLK (in), 12 5Q (out), 13 5D (in), 14 6D (in), 15 6Q (out), 16 7Q (out), 17 7D (in), 18 8D (in), 19 8Q (out), 20 VCC (power) hidden to VCC
1 alternate drawing of the same symbol

## SN74LS280
designator U?
9-BIT ODD/EVEN PARITY GNR/CHKR
footprint DIP-14
footprint SO14
pins: 1 G (in), 2 H (in), 4 I (in), 5 (out), 6 (out), 7 GND (power) hidden to GND, 8 A (in), 9 B (in), 10 C (in), 11 D (in), 12 E (in), 13 F (in), 14 VCC (power) hidden to VCC
1 alternate drawing of the same symbol

## SN74LS283
designator U?
4-BIT BIN ADD WITH FC
footprint SO16
footprint DIP-16
pins: 1 (out), 2 B2 (in), 3 A2 (in), 4 (out), 5 A1 (in), 6 B1 (in), 7 CO (in), 8 GND (power) hidden to GND, 9 C4 (out), 10 (out), 11 B4 (in), 12 A4 (in), 13 (out), 14 A3 (in), 15 B3 (in), 16 VCC (power) hidden to VCC
1 alternate drawing of the same symbol

## SN74LS290
designator U?
DECADE AND 4-BIT BIN CNT
footprint DIP-14
footprint SO14
pins: 1 R9(1) (in), 3 R9(2) (in), 4 QC (out), 5 QB (out), 7 GND (power) hidden to GND, 8 QD (out), 9 QA (out), 10 CKA (in), 11 CKB (in), 12 R0(1) (in), 13 R0(2) (in), 14 VCC (power) hidden to VCC
1 alternate drawing of the same symbol

## SN74LS292
designator U?
PROGRAMMABLE FRQ DIV/DIGITAL TIMERS
footprint DIP-16
pins: 1 B (in), 2 E (in), 3 TP1 (out), 4 CLK1 (in), 5 CLK2 (in), 6 TP2 (out), 7 Q (out), 8 GND (power) hidden to GND, 10 A (in), 11 ~{CLR} (in), 13 TP3 (out), 14 D (in), 15 C (in), 16 VCC (power) hidden to VCC
1 alternate drawing of the same symbol

## SN74LS294
designator U?
PROGRAMMABLE FRQ DIV/DIGITAL TIMERS
footprint DIP-16
pins: 1 B (in), 2 A (in), 3 TP (out), 4 CLK1 (in), 5 CLK2 (in), 7 Q (out), 8 GND (power) hidden to GND, 11 ~{CLR} (in), 14 D (in), 15 C (in), 16 VCC (power) hidden to VCC
1 alternate drawing of the same symbol

## SN74LS298
designator U?
QUAD 2-IN MUX WITH STORAGE
footprint SO16
footprint DIP-16
pins: 1 B2 (in), 2 A2 (in), 3 A1 (in), 4 B1 (in), 5 C2 (in), 6 D2 (in), 7 D1 (in), 8 GND (power) hidden to GND, 9 C1 (in), 10 WS (in), 11 CLK (in), 12 QD (out), 13 QC (out), 14 QB (out), 15 QA (out), 16 VCC (power) hidden to VCC
1 alternate drawing of the same symbol

## SN74LS299
designator U?
8-BIT UNIVERSAL SFT/STORAGE REG
footprint DIP-20
footprint SO20W
pins: 1 S0 (in), 2 ~{G}1 (in), 3 ~{G}2 (in), 4 G/QG (in), 5 E/QE (in), 6 C/QC (in), 7 A/QA (in), 8 QA (out), 9 CLR (in), 10 GND (power) hidden to GND, 11 SR (in), 12 CLK (in), 13 B/QB (in), 14 D/QD (in), 15 F/QF (in), 16 H/QH (in), 17 QH (out), 18 SL (in), 19 S1 (in), 20 VCC (power) hidden to VCC
1 alternate drawing of the same symbol

## SN74LS320
designator U?
CRYSTAL-CONTROLLED OSCILLATOR
footprint DIP-16
pins: 1 TANK1, 2 TANK2, 4 FFQ (out), 5 FFD (in), 7 F (out), 8 GND (power) hidden to GND, 9 ~{F}1 (out), 10 F1 (out), 11 VCC1 (power) hidden to VCC1, 12 ~{F} (out), 14 XTAL1, 15 XTAL2, 16 VCC (power) hidden to VCC
1 alternate drawing of the same symbol

## SN74LS321
designator U?
CRYSTAL-CONTROLLED OSCILLATOR
footprint DIP-16
pins: 1 TANK1, 2 TANK2, 4 FFQ (out), 5 FFD (in), 6 F/4 (out), 7 F (out), 8 GND (power) hidden to GND, 9 ~{F}1 (out), 10 F1 (out), 11 VCC1 (power) hidden to VCC1, 12 ~{F} (out), 13 F/2 (out), 14 XTAL1, 15 XTAL2, 16 VCC (power) hidden to VCC
1 alternate drawing of the same symbol

## SN74LS322A
designator U?
8-BIT REG WITH SIGN EXTEND REG
footprint SO20W
footprint DIP-20
pins: 1 ~{G} (in), 2 S/~{P} (in), 3 D0 (in), 4 A/QA (in), 5 C/QC (in), 6 E/QE (in), 7 G/QG (in), 8 ~{OE} (in), 9 CLR (in), 10 GND (power) hidden to GND, 11 CLK (in), 12 QH (out), 13 H/QH (in), 14 F/QF (in), 15 D/QD (in), 16 B/QB (in), 17 D1 (in), 18 ~{SE} (in), 19 DS (in), 20 VCC (power) hidden to VCC
1 alternate drawing of the same symbol

## SN74LS323
designator U?
8-BIT UNIVERSAL SFT/STORAGE REG
footprint DIP-20
footprint SO20W
pins: 1 S0 (in), 2 ~{G}1 (in), 3 ~{G}2 (in), 4 G/QG (in), 5 E/QE (in), 6 C/QC (in), 7 A/QA (in), 8 QA (out), 9 CLR (in), 10 GND (power) hidden to GND, 11 SR (in), 12 CLK (in), 13 B/QB (in), 14 D/QD (in), 15 F/QF (in), 16 H/QH (in), 17 QH (out), 18 SL (in), 19 S1 (in), 20 VCC (power) hidden to VCC
1 alternate drawing of the same symbol

## SN74LS348
designator U?
8-TO-3 PRIORITY ENCODER 3SO
footprint DIP-16
footprint SO16
pins: 1 4 (in), 2 5 (in), 3 6 (in), 4 7 (in), 5 EI (in), 6 A2 (hiz), 7 A1 (hiz), 8 GND (power) hidden to GND, 9 AO (hiz), 10 0 (in), 11 1 (in), 12 2 (in), 13 3 (in), 14 GS (out), 15 EO (out), 16 VCC (power) hidden to VCC
1 alternate drawing of the same symbol

## SN74LS352
designator U?
DUAL 4-1LINES DATA SLCR/MUX
footprint DIP-16
footprint SO16
pins: 1 1~{G} (in), 2 B (in), 3 1C3 (in), 4 1C2 (in), 5 1C1 (in), 6 1C0 (in), 7 1Y (out), 8 GND (power) hidden to GND, 9 2Y (out), 10 2C0 (in), 11 2C1 (in), 12 2C2 (in), 13 2C3 (in), 14 A (in), 15 2~{G} (in), 16 VCC (power) hidden to VCC
1 alternate drawing of the same symbol

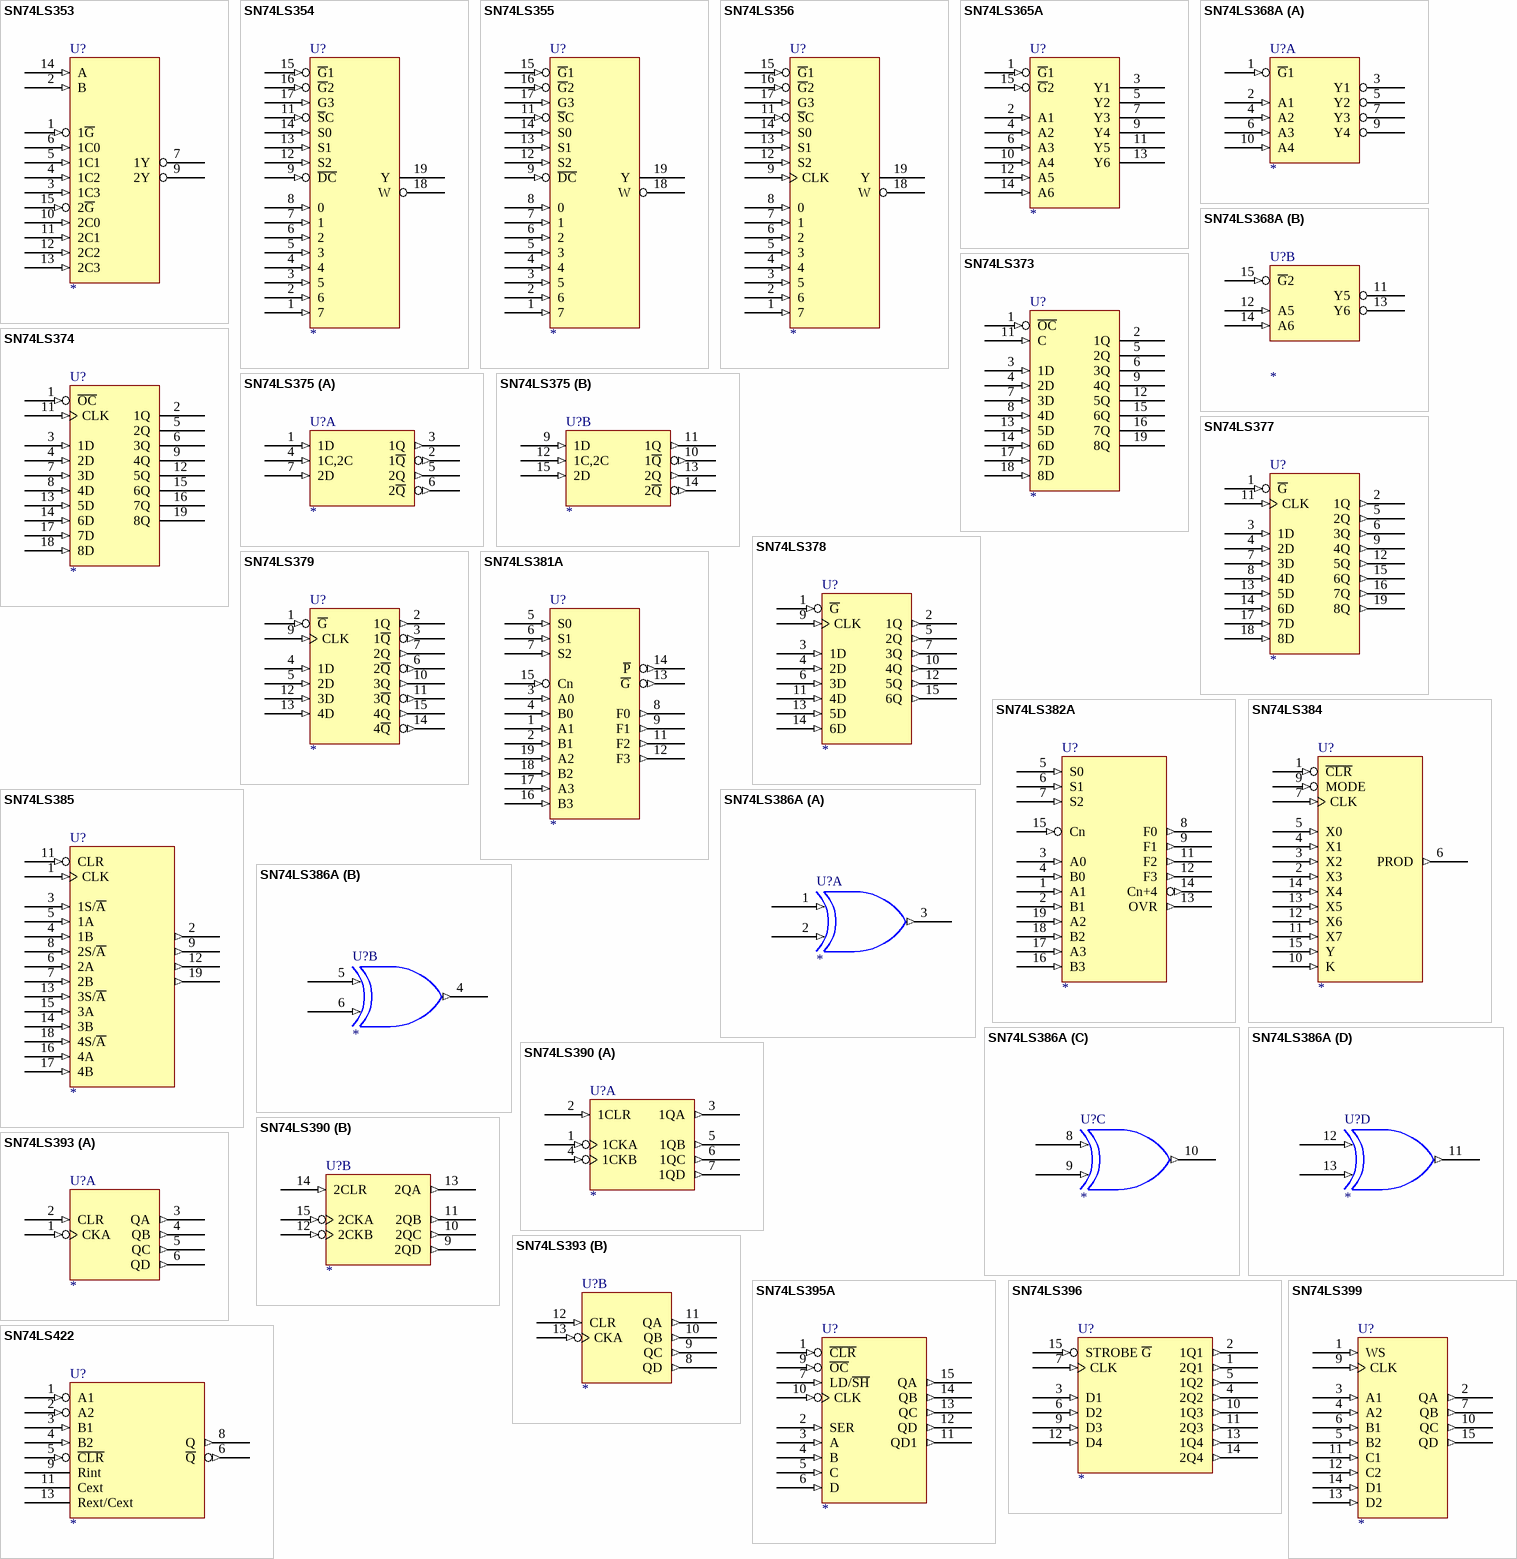
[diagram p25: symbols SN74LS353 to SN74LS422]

## SN74LS353
designator U?
DUAL 4-1LINES DATA SLCR/MUX 3SO
footprint SO16
footprint DIP-16
pins: 1 1~{G} (in), 2 B (in), 3 1C3 (in), 4 1C2 (in), 5 1C1 (in), 6 1C0 (in), 7 1Y (hiz), 8 GND (power) hidden to GND, 9 2Y (hiz), 10 2C0 (in), 11 2C1 (in), 12 2C2 (in), 13 2C3 (in), 14 A (in), 15 2~{G} (in), 16 VCC (power) hidden to VCC
1 alternate drawing of the same symbol

## SN74LS354
designator U?
8-1LINE DATA SLCR/MUX/REG
footprint SO20W
footprint DIP-20
pins: 1 7 (in), 2 6 (in), 3 5 (in), 4 (in), 5 3 (in), 6 2 (in), 7 1 (in), 8 0 (in), 9 ~{DC} (in), 10 GND (power) hidden to GND, 11 ~{S}C (in), 12 S2 (in), 13 S1 (in), 14 S0 (in), 15 ~{G}1 (in), 16 ~{G}2 (in), 17 G3 (in), 18 W (hiz), 19 Y (hiz), 20 VCC (power) hidden to VCC
1 alternate drawing of the same symbol

## SN74LS355
designator U?
8-1LINE DATA SLCR/MUX/REG
footprint SO20W
footprint DIP-20
pins: 1 7 (in), 2 6 (in), 3 5 (in), 4 (in), 5 3 (in), 6 2 (in), 7 1 (in), 8 0 (in), 9 ~{DC} (in), 10 GND (power) hidden to GND, 11 ~{S}C (in), 12 S2 (in), 13 S1 (in), 14 S0 (in), 15 ~{G}1 (in), 16 ~{G}2 (in), 17 G3 (in), 18 W (oc), 19 Y (oc), 20 VCC (power) hidden to VCC
1 alternate drawing of the same symbol

## SN74LS356
designator U?
8-1LINE DATA SLCR/MUX/REG
footprint DIP-20
footprint SO20W
pins: 1 7 (in), 2 6 (in), 3 5 (in), 4 (in), 5 3 (in), 6 2 (in), 7 1 (in), 8 0 (in), 9 CLK (in), 10 GND (power) hidden to GND, 11 ~{S}C (in), 12 S2 (in), 13 S1 (in), 14 S0 (in), 15 ~{G}1 (in), 16 ~{G}2 (in), 17 G3 (in), 18 W (hiz), 19 Y (hiz), 20 VCC (power) hidden to VCC
1 alternate drawing of the same symbol

## SN74LS365A
designator U?
HEX BUS DRV 3SO
footprint SO16
footprint DIP-16
pins: 1 ~{G}1 (in), 2 A1 (in), 3 Y1 (hiz), 4 A2 (in), 5 Y2 (hiz), 6 A3 (in), 7 Y3 (hiz), 8 GND (power) hidden to GND, 9 Y4 (hiz), 10 A4 (in), 11 Y5 (hiz), 12 A5 (in), 13 Y6 (hiz), 14 A6 (in), 15 ~{G}2 (in), 16 VCC (power) hidden to VCC
1 alternate drawing of the same symbol

## SN74LS368A
designator U?
HEX BUS DRV 3SO
footprint SO16
footprint DIP-16
part A pins: 1 ~{G}1 (in), 2 A1 (in), 3 Y1 (hiz), 4 A2 (in), 5 Y2 (hiz), 6 A3 (in), 7 Y3 (hiz), 8 GND (power) hidden to GND, 9 Y4 (hiz), 10 A4 (in), 16 VCC (power) hidden to VCC
part B pins: 8 GND (power) hidden to GND, 11 Y5 (hiz), 12 A5 (in), 13 Y6 (hiz), 14 A6 (in), 15 ~{G}2 (in), 16 VCC (power) hidden to VCC
1 alternate drawing of the same symbol

## SN74LS373
designator U?
OCTAL TRANSPARENT LCH
footprint DIP-20
pins: 1 ~{OC} (in), 2 1Q (hiz), 3 1D (in), 4 2D (in), 5 2Q (hiz), 6 3Q (hiz), 7 3D (in), 8 4D (in), 9 4Q (hiz), 10 GND (power) hidden to GND, 11 C (in), 12 5Q (hiz), 13 5D (in), 14 6D (in), 15 6Q (hiz), 16 7Q (hiz), 17 7D (in), 18 8D (in), 19 8Q (hiz), 20 VCC (power) hidden to VCC
1 alternate drawing of the same symbol

## SN74LS374
designator U?
OCTAL D-TYPE EDGE TRIGGERED FF 3SO
footprint DIP-20
pins: 1 ~{OC} (in), 2 1Q (hiz), 3 1D (in), 4 2D (in), 5 2Q (hiz), 6 3Q (hiz), 7 3D (in), 8 4D (in), 9 4Q (hiz), 10 GND (power) hidden to GND, 11 CLK (in), 12 5Q (hiz), 13 5D (in), 14 6D (in), 15 6Q (hiz), 16 7Q (hiz), 17 7D (in), 18 8D (in), 19 8Q (hiz), 20 VCC (power) hidden to VCC
1 alternate drawing of the same symbol

## SN74LS375
designator U?
4-BIT BISTABLE LCH
footprint SO16
footprint DIP-16
part A pins: 1 1D (in), 2 1~{Q} (out), 3 1Q (out), 4 1C,2C (in), 5 2Q (out), 6 2~{Q} (out), 7 2D (in), 8 GND (power) hidden to GND, 16 VCC (power) hidden to VCC
part B pins: 8 GND (power) hidden to GND, 9 1D (in), 10 1~{Q} (out), 11 1Q (out), 12 1C,2C (in), 13 2Q (out), 14 2~{Q} (out), 15 2D (in), 16 VCC (power) hidden to VCC
1 alternate drawing of the same symbol

## SN74LS377
designator U?
OCTAL D-TYPE FF WITH ENABLE
footprint DIP-20
footprint SO20W
pins: 1 ~{G} (in), 2 1Q (out), 3 1D (in), 4 2D (in), 5 2Q (out), 6 3Q (out), 7 3D (in), 8 4D (in), 9 4Q (out), 10 GND (power) hidden to GND, 11 CLK (in), 12 5Q (out), 13 5D (in), 14 6D (in), 15 6Q (out), 16 7Q (out), 17 7D (in), 18 8D (in), 19 8Q (out), 20 VCC (power) hidden to VCC
1 alternate drawing of the same symbol

## SN74LS378
designator U?
HEX D-TYPE FF WITH ENABLE
footprint SO16
footprint DIP-16
pins: 1 ~{G} (in), 2 1Q (out), 3 1D (in), 4 2D (in), 5 2Q (out), 6 3D (in), 7 3Q (out), 8 GND (power) hidden to GND, 9 CLK (in), 10 4Q (out), 11 4D (in), 12 5Q (out), 13 5D (in), 14 6D (in), 15 6Q (out), 16 VCC (power) hidden to VCC
1 alternate drawing of the same symbol

## SN74LS379
designator U?
QUAD D-TYPE FF WITH ENABLE
footprint DIP-16
footprint SO16
pins: 1 ~{G} (in), 2 1Q (out), 3 1~{Q} (out), 4 1D (in), 5 2D (in), 6 2~{Q} (out), 7 2Q (out), 8 GND (power) hidden to GND, 9 CLK (in), 10 3Q (out), 11 3~{Q} (out), 12 3D (in), 13 4D (in), 14 4~{Q} (out), 15 4Q (out), 16 VCC (power) hidden to VCC
1 alternate drawing of the same symbol

## SN74LS381A
designator U?
ALU/FN GNR
footprint SO20W
footprint DIP-20
footprint SO16W
pins: 1 A1 (in), 2 B1 (in), 3 A0 (in), 4 B0 (in), 5 S0 (in), 6 S1 (in), 7 S2 (in), 8 F0 (out), 9 F1 (out), 10 GND (power) hidden to GND, 11 F2 (out), 12 F3 (out), 13 ~{G} (out), 14 ~{P} (out), 15 Cn (in), 16 B3 (in), 17 A3 (in), 18 B2 (in), 19 A2 (in), 20 VCC (power) hidden to VCC
1 alternate drawing of the same symbol

## SN74LS382A
designator U?
ALU/FN GNR
footprint DIP-20
footprint SO20W
pins: 1 A1 (in), 2 B1 (in), 3 A0 (in), 4 B0 (in), 5 S0 (in), 6 S1 (in), 7 S2 (in), 8 F0 (out), 9 F1 (out), 10 GND (power) hidden to GND, 11 F2 (out), 12 F3 (out), 13 OVR (out), 14 Cn+4 (out), 15 Cn (in), 16 B3 (in), 17 A3 (in), 18 B2 (in), 19 A2 (in), 20 VCC (power) hidden to VCC
1 alternate drawing of the same symbol

## SN74LS384
designator U?
8-BY-1-BIT TWO COMPLEMENT MULT
footprint DIP-16
pins: 1 ~{CLR} (in), 2 X3 (in), 3 X2 (in), 4 X1 (in), 5 X0 (in), 6 PROD (out), 7 CLK (in), 8 GND (power) hidden to GND, 9 MODE (in), 10 K (in), 11 X7 (in), 12 X6 (in), 13 X5 (in), 14 X4 (in), 15 Y (in), 16 VCC (power) hidden to VCC
1 alternate drawing of the same symbol

## SN74LS385
designator U?
QUAD SER ADDER/SUBTRACTER
footprint DIP-20
footprint SO20W
pins: 1 CLK (in), 2 (out), 3 1S/~{A} (in), 4 1B (in), 5 1A (in), 6 2A (in), 7 2B (in), 8 2S/~{A} (in), 9 (out), 10 GND (power) hidden to GND, 11 CLR (in), 12 (out), 13 3S/~{A} (in), 14 3B (in), 15 3A (in), 16 4A (in), 17 4B (in), 18 4S/~{A} (in), 19 (out), 20 VCC (power) hidden to VCC
1 alternate drawing of the same symbol

## SN74LS386A
designator U?
QUAD 2-IN XOR
footprint DIP-14
footprint SO14
part A pins: 1 (in), 2 (in), 3 (out), 7 GND (power) hidden to GND, 14 VCC (power) hidden to VCC
part B pins: 4 (out), 5 (in), 6 (in), 7 GND (power) hidden to GND, 14 VCC (power) hidden to VCC
part C pins: 7 GND (power) hidden to GND, 8 (in), 9 (in), 10 (out), 14 VCC (power) hidden to VCC
part D pins: 7 GND (power) hidden to GND, 11 (out), 12 (in), 13 (in), 14 VCC (power) hidden to VCC
1 alternate drawing of the same symbol

## SN74LS390
designator U?
DUAL 4-BIT AND BIN CNT
footprint SO16
footprint DIP-16
part A pins: 1 1CKA (in), 2 1CLR (in), 3 1QA (out), 4 1CKB (in), 5 1QB (out), 6 1QC (out), 7 1QD (out), 8 GND (power) hidden to GND, 16 VCC (power) hidden to VCC
part B pins: 8 GND (power) hidden to GND, 9 2QD (out), 10 2QC (out), 11 2QB (out), 12 2CKB (in), 13 2QA (out), 14 2CLR (in), 15 2CKA (in), 16 VCC (power) hidden to VCC
1 alternate drawing of the same symbol

## SN74LS393
designator U?
DUAL 4-BIT AND BIN CNT
footprint DIP-14
part A pins: 1 CKA (in), 2 CLR (in), 3 QA (out), 4 QB (out), 5 QC (out), 6 QD (out), 7 GND (power) hidden to GND, 14 VCC (power) hidden to VCC
part B pins: 7 GND (power) hidden to GND, 8 QD (out), 9 QC (out), 10 QB (out), 11 QA (out), 12 CLR (in), 13 CKA (in), 14 VCC (power) hidden to VCC
1 alternate drawing of the same symbol

## SN74LS395A
designator U?
4-BIT CASCADABLE SFT REG 3SO
footprint SO16
footprint DIP-16
pins: 1 ~{CLR} (in), 2 SER (in), 3 A (in), 4 B (in), 5 C (in), 6 D (in), 7 LD/~{SH} (in), 8 GND (power) hidden to GND, 9 ~{OC} (in), 10 CLK (in), 11 QD1 (out), 12 QD (out), 13 QC (out), 14 QB (out), 15 QA (out), 16 VCC (power) hidden to VCC
1 alternate drawing of the same symbol

## SN74LS396
designator U?
OCTAL STORAGE REG
footprint SO16
footprint DIP-16
pins: 1 2Q1 (out), 2 1Q1 (out), 3 D1 (in), 4 2Q2 (out), 5 1Q2 (out), 6 D2 (in), 7 CLK (in), 8 GND (power) hidden to GND, 9 D3 (in), 10 1Q3 (out), 11 2Q3 (out), 12 D4 (in), 13 1Q4 (out), 14 2Q4 (out), 15 STROBE ~{G} (in), 16 VCC (power) hidden to VCC
1 alternate drawing of the same symbol

## SN74LS399
designator U?
QUAD 2-IN MUX WITH STORAGE
footprint SO16
footprint DIP-16
pins: 1 WS (in), 2 QA (out), 3 A1 (in), 4 A2 (in), 5 B2 (in), 6 B1 (in), 7 QB (out), 8 GND (power) hidden to GND, 9 CLK (in), 10 QC (out), 11 C1 (in), 12 C2 (in), 13 D2 (in), 14 D1 (in), 15 QD (out), 16 VCC (power) hidden to VCC
1 alternate drawing of the same symbol

## SN74LS422
designator U?
RETRIGGERABLE MONOSTABLE MULTIVIBRATOR
footprint SO14
footprint DIP-14
pins: 1 A1 (in), 2 A2 (in), 3 B1 (in), 4 B2 (in), 5 ~{CLR} (in), 6 ~{Q} (out), 7 GND (power) hidden to GND, 8 Q (out), 9 Rint, 11 Cext, 13 Rext/Cext, 14 VCC (power) hidden to VCC
1 alternate drawing of the same symbol

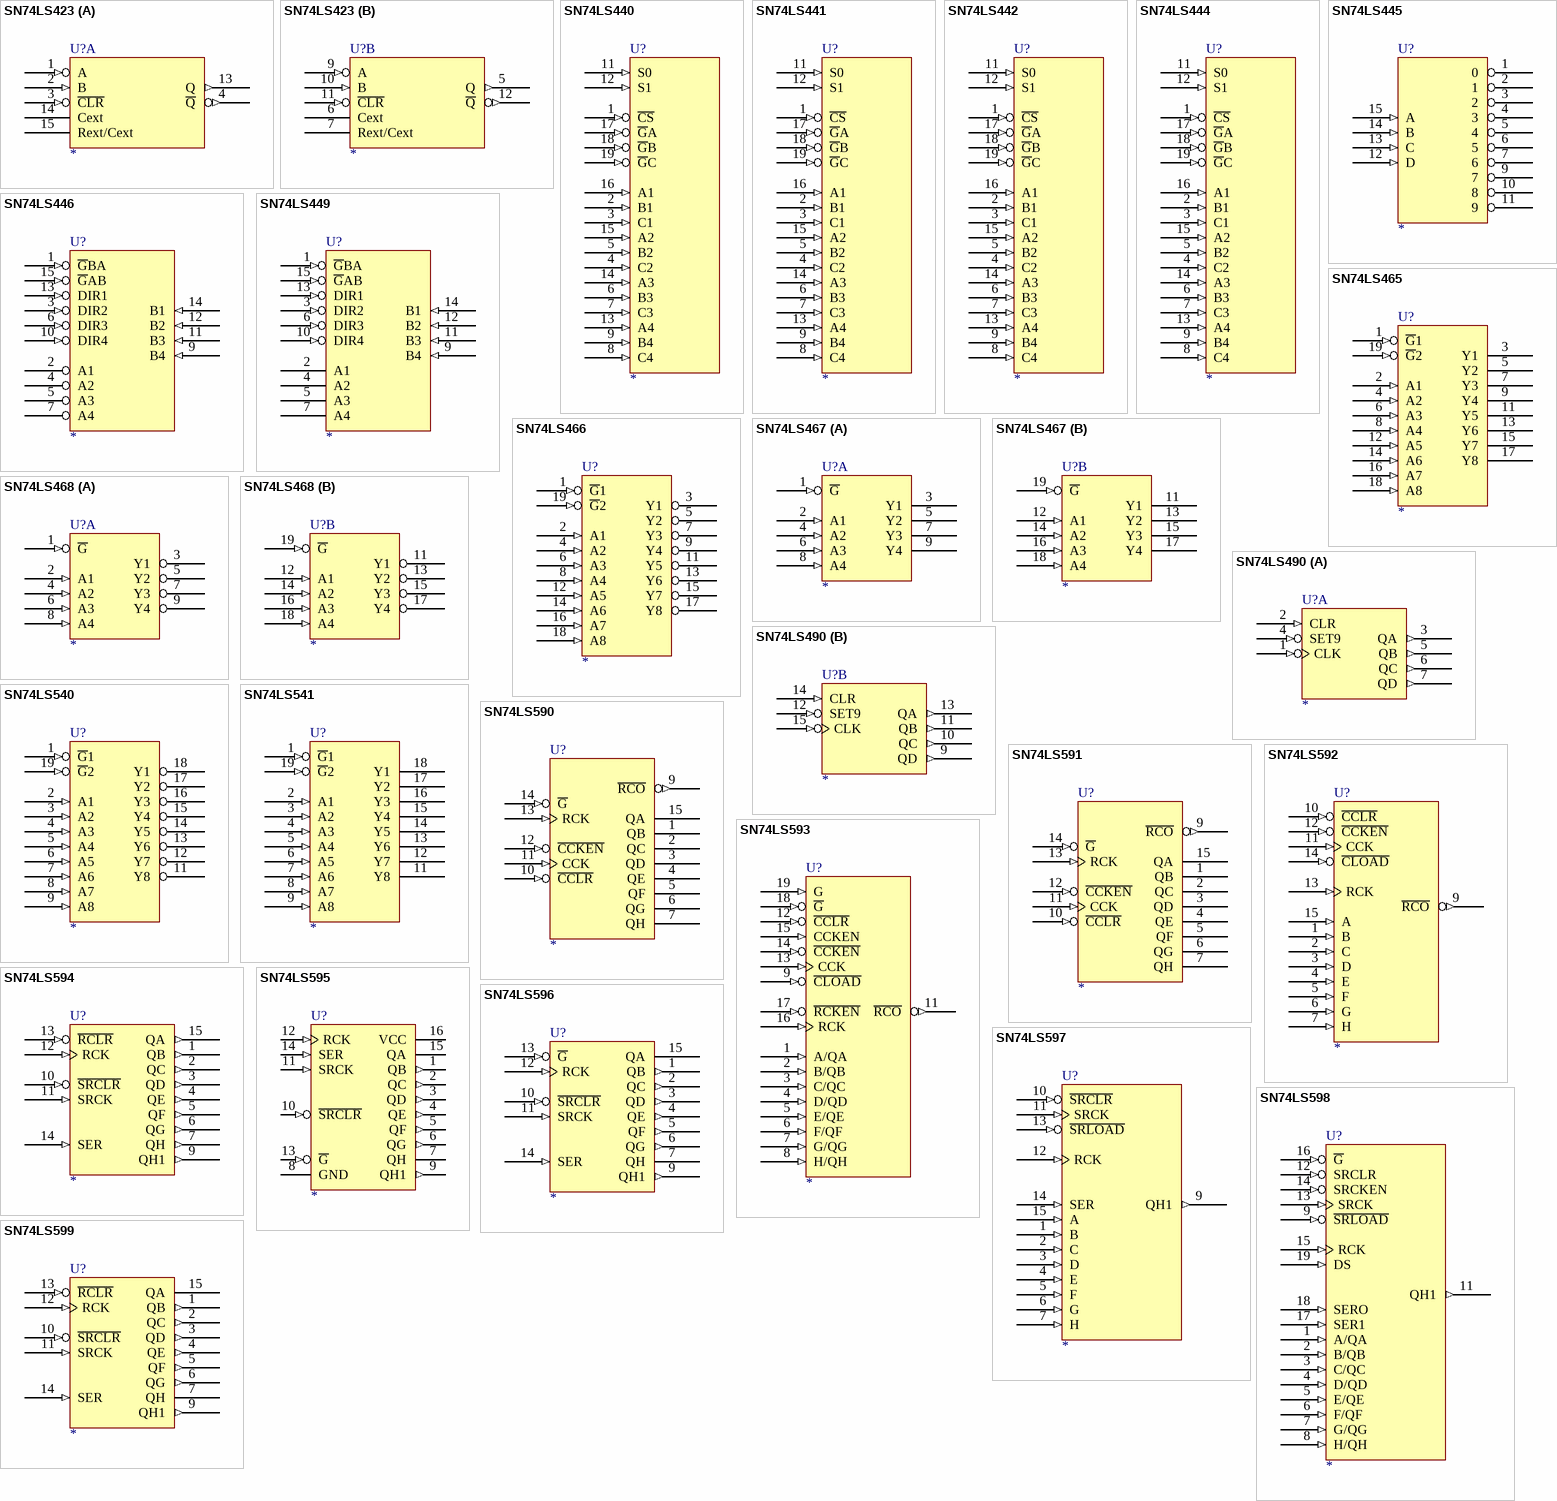
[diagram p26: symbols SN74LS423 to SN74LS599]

## SN74LS423
designator U?
RETRIGGERABLE MONOSTABLE MULTIVIBRATOR
footprint SO16
footprint DIP-16
part A pins: 1 A (in), 2 B (in), 3 ~{CLR} (in), 4 ~{Q} (out), 8 GND (power) hidden to GND, 13 Q (out), 14 Cext, 15 Rext/Cext, 16 VCC (power) hidden to VCC
part B pins: 5 Q (out), 6 Cext, 7 Rext/Cext, 8 GND (power) hidden to GND, 9 A (in), 10 B (in), 11 ~{CLR} (in), 12 ~{Q} (out), 16 VCC (power) hidden to VCC
1 alternate drawing of the same symbol

## SN74LS440
designator U?
QUAD TRIDIRECTIONAL BUS TRANSCEIVERS
footprint SO20W
footprint DIP-20
pins: 1 ~{CS} (in), 2 B1 (in), 3 C1 (in), 4 C2 (in), 5 B2 (in), 6 B3 (in), 7 C3 (in), 8 C4 (in), 9 B4 (in), 10 GND (power) hidden to GND, 11 S0 (in), 12 S1 (in), 13 A4 (in), 14 A3 (in), 15 A2 (in), 16 A1 (in), 17 ~{G}A (in), 18 ~{G}B (in), 19 ~{G}C (in), 20 VCC (power) hidden to VCC
1 alternate drawing of the same symbol

## SN74LS441
designator U?
QUAD TRIDIRECTIONAL BUS TRANSCEIVERS
footprint DIP-20
footprint SO20W
pins: 1 ~{CS} (in), 2 B1 (in), 3 C1 (in), 4 C2 (in), 5 B2 (in), 6 B3 (in), 7 C3 (in), 8 C4 (in), 9 B4 (in), 10 GND (power) hidden to GND, 11 S0 (in), 12 S1 (in), 13 A4 (in), 14 A3 (in), 15 A2 (in), 16 A1 (in), 17 ~{G}A (in), 18 ~{G}B (in), 19 ~{G}C (in), 20 VCC (power) hidden to VCC
1 alternate drawing of the same symbol

## SN74LS442
designator U?
QUAD TRIDIRECTIONAL BUS TRANSCEIVERS
footprint SO20W
footprint DIP-20
pins: 1 ~{CS} (in), 2 B1 (in), 3 C1 (in), 4 C2 (in), 5 B2 (in), 6 B3 (in), 7 C3 (in), 8 C4 (in), 9 B4 (in), 10 GND (power) hidden to GND, 11 S0 (in), 12 S1 (in), 13 A4 (in), 14 A3 (in), 15 A2 (in), 16 A1 (in), 17 ~{G}A (in), 18 ~{G}B (in), 19 ~{G}C (in), 20 VCC (power) hidden to VCC
1 alternate drawing of the same symbol

## SN74LS444
designator U?
QUAD TRIDIRECTIONAL BUS TRANSCEIVERS
footprint SO20W
footprint DIP-20
pins: 1 ~{CS} (in), 2 B1 (in), 3 C1 (in), 4 C2 (in), 5 B2 (in), 6 B3 (in), 7 C3 (in), 8 C4 (in), 9 B4 (in), 10 GND (power) hidden to GND, 11 S0 (in), 12 S1 (in), 13 A4 (in), 14 A3 (in), 15 A2 (in), 16 A1 (in), 17 ~{G}A (in), 18 ~{G}B (in), 19 ~{G}C (in), 20 VCC (power) hidden to VCC
1 alternate drawing of the same symbol

## SN74LS445
designator U?
BCD-TO-DECIMAL DEC/DRV
footprint SO16
footprint DIP-16
pins: 1 0 (oc), 2 1 (oc), 3 2 (oc), 4 3 (oc), 5 4 (oc), 6 5 (oc), 7 6 (oc), 8 GND (power) hidden to GND, 9 7 (oc), 10 8 (oc), 11 9 (oc), 12 D (in), 13 C (in), 14 B (in), 15 A (in), 16 VCC (power) hidden to VCC
1 alternate drawing of the same symbol

## SN74LS446
designator U?
QUAD BUS TRANSCEIVER WITH INDIVIDUAL DIR CONTROL
footprint SO16
footprint DIP-16
pins: 1 ~{G}BA (in), 2 A1 (hiz), 3 DIR2 (in), 4 A2 (hiz), 5 A3 (hiz), 6 DIR3 (in), 7 A4 (hiz), 8 GND (power) hidden to GND, 9 B4 (in), 10 DIR4 (in), 11 B3 (in), 12 B2 (in), 13 DIR1 (in), 14 B1 (in), 15 ~{G}AB (in), 16 VCC (power) hidden to VCC
1 alternate drawing of the same symbol

## SN74LS449
designator U?
QUAD BUS TRANSCEIVER WITH INDIVIDUAL DIR CONTROL
footprint DIP-16
footprint SO16
pins: 1 ~{G}BA (in), 2 A1 (hiz), 3 DIR2 (in), 4 A2 (hiz), 5 A3 (hiz), 6 DIR3 (in), 7 A4 (hiz), 8 GND (power) hidden to GND, 9 B4 (in), 10 DIR4 (in), 11 B3 (in), 12 B2 (in), 13 DIR1 (in), 14 B1 (in), 15 ~{G}AB (in), 16 VCC (power) hidden to VCC
1 alternate drawing of the same symbol

## SN74LS465
designator U?
OCTAL BUF 3SO
footprint SO20W
footprint DIP-20
pins: 1 ~{G}1 (in), 2 A1 (in), 3 Y1 (hiz), 4 A2 (in), 5 Y2 (hiz), 6 A3 (in), 7 Y3 (hiz), 8 A4 (in), 9 Y4 (hiz), 10 GND (power) hidden to GND, 11 Y5 (hiz), 12 A5 (in), 13 Y6 (hiz), 14 A6 (in), 15 Y7 (hiz), 16 A7 (in), 17 Y8 (hiz), 18 A8 (in), 19 ~{G}2 (in), 20 VCC (power) hidden to VCC
1 alternate drawing of the same symbol

## SN74LS466
designator U?
OCTAL BUF 3SO
footprint DIP-20
footprint SO20W
pins: 1 ~{G}1 (in), 2 A1 (in), 3 Y1 (hiz), 4 A2 (in), 5 Y2 (hiz), 6 A3 (in), 7 Y3 (hiz), 8 A4 (in), 9 Y4 (hiz), 10 GND (power) hidden to GND, 11 Y5 (hiz), 12 A5 (in), 13 Y6 (hiz), 14 A6 (in), 15 Y7 (hiz), 16 A7 (in), 17 Y8 (hiz), 18 A8 (in), 19 ~{G}2 (in), 20 VCC (power) hidden to VCC
1 alternate drawing of the same symbol

## SN74LS467
designator U?
OCTAL BUF 3SO
footprint DIP-20
footprint SO20W
part A pins: 1 ~{G} (in), 2 A1 (in), 3 Y1 (hiz), 4 A2 (in), 5 Y2 (hiz), 6 A3 (in), 7 Y3 (hiz), 8 A4 (in), 9 Y4 (hiz), 10 GND (power) hidden to GND, 20 VCC (power) hidden to VCC
part B pins: 10 GND (power) hidden to GND, 11 Y1 (hiz), 12 A1 (in), 13 Y2 (hiz), 14 A2 (in), 15 Y3 (hiz), 16 A3 (in), 17 Y4 (hiz), 18 A4 (in), 19 ~{G} (in), 20 VCC (power) hidden to VCC
1 alternate drawing of the same symbol

## SN74LS468
designator U?
OCTAL BUF 3SO
footprint DIP-20
footprint SO20W
part A pins: 1 ~{G} (in), 2 A1 (in), 3 Y1 (hiz), 4 A2 (in), 5 Y2 (hiz), 6 A3 (in), 7 Y3 (hiz), 8 A4 (in), 9 Y4 (hiz), 10 GND (power) hidden to GND, 20 VCC (power) hidden to VCC
part B pins: 10 GND (power) hidden to GND, 11 Y1 (hiz), 12 A1 (in), 13 Y2 (hiz), 14 A2 (in), 15 Y3 (hiz), 16 A3 (in), 17 Y4 (hiz), 18 A4 (in), 19 ~{G} (in), 20 VCC (power) hidden to VCC
1 alternate drawing of the same symbol

## SN74LS490
designator U?
DUAL 4-BIT AND BIN CNT
footprint SO16
footprint DIP-16
part A pins: 1 CLK (in), 2 CLR (in), 3 QA (out), 4 SET9 (in), 5 QB (out), 6 QC (out), 7 QD (out), 8 GND (power) hidden to GND, 16 VCC (power) hidden to VCC
part B pins: 8 GND (power) hidden to GND, 9 QD (out), 10 QC (out), 11 QB (out), 12 SET9 (in), 13 QA (out), 14 CLR (in), 15 CLK (in), 16 VCC (power) hidden to VCC
1 alternate drawing of the same symbol

## SN74LS540
designator U?
OCTAL BUF AND LINE DRV 3SO
footprint SO20W
footprint DIP-20
pins: 1 ~{G}1 (in), 2 A1 (in), 3 A2 (in), 4 A3 (in), 5 A4 (in), 6 A5 (in), 7 A6 (in), 8 A7 (in), 9 A8 (in), 10 GND (power) hidden to GND, 11 Y8 (hiz), 12 Y7 (hiz), 13 Y6 (hiz), 14 Y5 (hiz), 15 Y4 (hiz), 16 Y3 (hiz), 17 Y2 (hiz), 18 Y1 (hiz), 19 ~{G}2 (in), 20 VCC (power) hidden to VCC
1 alternate drawing of the same symbol

## SN74LS541
designator U?
OCTAL BUF AND LINE DRV 3SO
footprint SO20W
footprint DIP-20
pins: 1 ~{G}1 (in), 2 A1 (in), 3 A2 (in), 4 A3 (in), 5 A4 (in), 6 A5 (in), 7 A6 (in), 8 A7 (in), 9 A8 (in), 10 GND (power) hidden to GND, 11 Y8 (hiz), 12 Y7 (hiz), 13 Y6 (hiz), 14 Y5 (hiz), 15 Y4 (hiz), 16 Y3 (hiz), 17 Y2 (hiz), 18 Y1 (hiz), 19 ~{G}2 (in), 20 VCC (power) hidden to VCC
1 alternate drawing of the same symbol

## SN74LS590
designator U?
8-BIT BIN CNT WITH OUTPUT REGISTERS
footprint DIP-16
pins: 1 QB (hiz), 2 QC (hiz), 3 QD (hiz), 4 QE (hiz), 5 QF (hiz), 6 QG (hiz), 7 QH (hiz), 8 GND (power) hidden to GND, 9 ~{RCO} (out), 10 ~{CCLR} (in), 11 CCK (in), 12 ~{CCKEN} (in), 13 RCK (in), 14 ~{G} (in), 15 QA (hiz), 16 VCC (power) hidden to VCC
1 alternate drawing of the same symbol

## SN74LS591
designator U?
8-BIT BIN CNT WITH OUTPUT REGISTERS
footprint DIP-16
pins: 1 QB (oc), 2 QC (oc), 3 QD (oc), 4 QE (oc), 5 QF (oc), 6 QG (oc), 7 QH (oc), 8 GND (power) hidden to GND, 9 ~{RCO} (out), 10 ~{CCLR} (in), 11 CCK (in), 12 ~{CCKEN} (in), 13 RCK (in), 14 ~{G} (in), 15 QA (oc), 16 VCC (power) hidden to VCC
1 alternate drawing of the same symbol

## SN74LS592
designator U?
8-BIT BIN CNT WITH INPUT REG
footprint DIP-16
pins: 1 B (in), 2 C (in), 3 D (in), 4 E (in), 5 F (in), 6 G (in), 7 H (in), 8 GND (power) hidden to GND, 9 ~{RCO} (out), 10 ~{CCLR} (in), 11 CCK (in), 12 ~{CCKEN} (in), 13 RCK (in), 14 ~{CLOAD} (in), 15 A (in), 16 VCC (power) hidden to VCC
1 alternate drawing of the same symbol

## SN74LS593
designator U?
8-BIT BIN CNT WITH INPUT REG
footprint SO20W
footprint DIP-20
pins: 1 A/QA (in), 2 B/QB (in), 3 C/QC (in), 4 D/QD (in), 5 E/QE (in), 6 F/QF (in), 7 G/QG (in), 8 H/QH (in), 9 ~{CLOAD} (in), 10 GND (power) hidden to GND, 11 ~{RCO} (out), 12 ~{CCLR} (in), 13 CCK (in), 14 ~{CCKEN} (in), 15 CCKEN (in), 16 RCK (in), 17 ~{RCKEN} (in), 18 ~{G} (in), 19 G (in), 20 VCC (power) hidden to VCC
1 alternate drawing of the same symbol

## SN74LS594
designator U?
8-BIT SFT REG WIRTH OUTPUT LCH
footprint DIP-16
pins: 1 QB (out), 2 QC (out), 3 QD (out), 4 QE (out), 5 QF (out), 6 QG (out), 7 QH (out), 8 GND (power) hidden to GND, 9 QH1 (out), 10 ~{SRCLR} (in), 11 SRCK (in), 12 RCK (in), 13 ~{RCLR} (in), 14 SER (in), 15 QA (out), 16 VCC (power) hidden to VCC
1 alternate drawing of the same symbol

## SN74LS595
designator U?
8-BIT SFT REG WIRTH OUTPUT LCH
footprint DIP-16
pins: 1 QB (out), 2 QC (out), 3 QD (out), 4 QE (out), 5 QF (out), 6 QG (out), 7 QH (hiz), 8 GND (power), 9 QH1 (out), 10 ~{SRCLR} (in), 11 SRCK (in), 12 RCK (in), 13 ~{G} (in), 14 SER (in), 15 QA (hiz), 16 VCC (power)
1 alternate drawing of the same symbol

## SN74LS596
designator U?
8-BIT SFT REG WIRTH OUTPUT LCH
footprint DIP-16
pins: 1 QB (out), 2 QC (out), 3 QD (out), 4 QE (out), 5 QF (out), 6 QG (out), 7 QH (oc), 8 GND (power) hidden to GND, 9 QH1 (out), 10 ~{SRCLR} (in), 11 SRCK (in), 12 RCK (in), 13 ~{G} (in), 14 SER (in), 15 QA (oc), 16 VCC (power) hidden to VCC
1 alternate drawing of the same symbol

## SN74LS597
designator U?
8-BIT SFT REG WITH INPUT LCH
footprint DIP-16
pins: 1 B (in), 2 C (in), 3 D (in), 4 E (in), 5 F (in), 6 G (in), 7 H (in), 8 GND (power) hidden to GND, 9 QH1 (out), 10 ~{SRCLR} (in), 11 SRCK (in), 12 RCK (in), 13 ~{SRLOAD} (in), 14 SER (in), 15 A (in), 16 VCC (power) hidden to VCC
1 alternate drawing of the same symbol

## SN74LS598
designator U?
8-BIT SRG WITH INPUT LCH
footprint SO20W
footprint DIP-20
pins: 1 A/QA (in), 2 B/QB (in), 3 C/QC (in), 4 D/QD (in), 5 E/QE (in), 6 F/QF (in), 7 G/QG (in), 8 H/QH (in), 9 ~{SRLOAD} (in), 10 GND (power) hidden to GND, 11 QH1 (out), 12 SRCLR (in), 13 SRCK (in), 14 SRCKEN (in), 15 RCK (in), 16 ~{G} (in), 17 SER1 (in), 18 SERO (in), 19 DS (in), 20 VCC (power) hidden to VCC
1 alternate drawing of the same symbol

## SN74LS599
designator U?
8-BIT SFT REG WIRTH OUTPUT LCH
footprint DIP-16
pins: 1 QB (out), 2 QC (out), 3 QD (out), 4 QE (out), 5 QF (out), 6 QG (out), 7 QH (oc), 8 GND (power) hidden to GND, 9 QH1 (out), 10 ~{SRCLR} (in), 11 SRCK (in), 12 RCK (in), 13 ~{RCLR} (in), 14 SER (in), 15 QA (oc), 16 VCC (power) hidden to VCC
1 alternate drawing of the same symbol

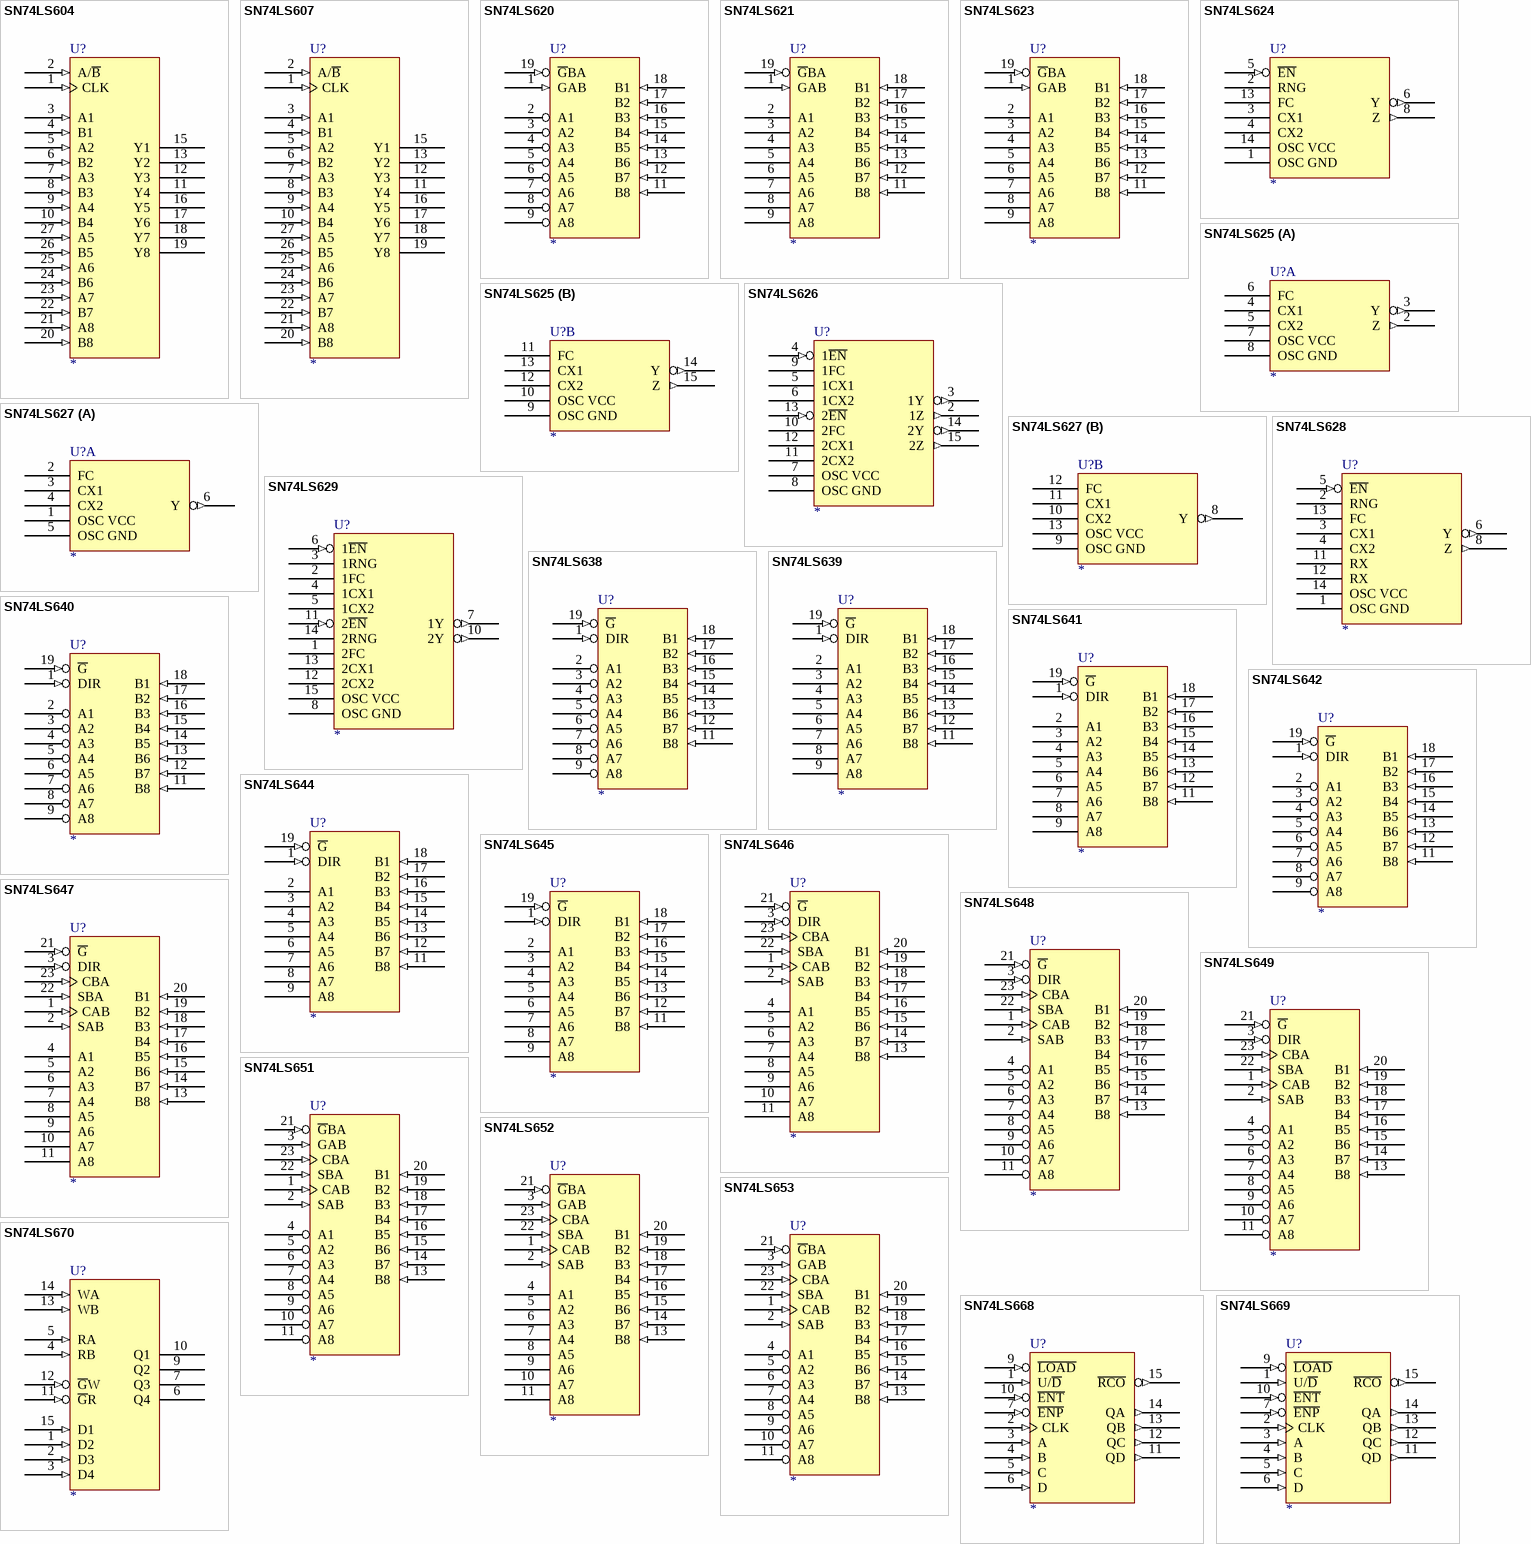
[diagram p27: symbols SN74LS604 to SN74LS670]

## SN74LS604
designator U?
OCTAL 2-IN MULTIPLEXED LCH
footprint DIP-28
footprint DIP-28
pins: 1 CLK (in), 2 A/~{B} (in), 3 A1 (in), 4 B1 (in), 5 A2 (in), 6 B2 (in), 7 A3 (in), 8 B3 (in), 9 A4 (in), 10 B4 (in), 11 Y4 (hiz), 12 Y3 (hiz), 13 Y2 (hiz), 14 GND (power) hidden to GND, 15 Y1 (hiz), 16 Y5 (hiz), 17 Y6 (hiz), 18 Y7 (hiz), 19 Y8 (hiz), 20 B8 (in), 21 A8 (in), 22 B7 (in), 23 A7 (in), 24 B6 (in), 25 A6 (in), 26 B5 (in), 27 A5 (in), 28 VCC (power) hidden to VCC
1 alternate drawing of the same symbol

## SN74LS607
designator U?
OCTAL 2-IN MULTIPLEXED LCH
footprint DIP-28
footprint DIP-28
pins: 1 CLK (in), 2 A/~{B} (in), 3 A1 (in), 4 B1 (in), 5 A2 (in), 6 B2 (in), 7 A3 (in), 8 B3 (in), 9 A4 (in), 10 B4 (in), 11 Y4 (oc), 12 Y3 (oc), 13 Y2 (oc), 14 GND (power) hidden to GND, 15 Y1 (oc), 16 Y5 (oc), 17 Y6 (oc), 18 Y7 (oc), 19 Y8 (oc), 20 B8 (in), 21 A8 (in), 22 B7 (in), 23 A7 (in), 24 B6 (in), 25 A6 (in), 26 B5 (in), 27 A5 (in), 28 VCC (power) hidden to VCC
1 alternate drawing of the same symbol

## SN74LS620
designator U?
OCTAL BUS TRANCEIVER
footprint SO20W
footprint DIP-20
pins: 1 GAB (in), 2 A1 (hiz), 3 A2 (hiz), 4 A3 (hiz), 5 A4 (hiz), 6 A5 (hiz), 7 A6 (hiz), 8 A7 (hiz), 9 A8 (hiz), 10 GND (power) hidden to GND, 11 B8 (in), 12 B7 (in), 13 B6 (in), 14 B5 (in), 15 B4 (in), 16 B3 (in), 17 B2 (in), 18 B1 (in), 19 ~{G}BA (in), 20 VCC (power) hidden to VCC
1 alternate drawing of the same symbol

## SN74LS621
designator U?
OCTAL BUS TRANCEIVER
footprint SO20W
footprint DIP-20
pins: 1 GAB (in), 2 A1 (oc), 3 A2 (oc), 4 A3 (oc), 5 A4 (oc), 6 A5 (oc), 7 A6 (oc), 8 A7 (oc), 9 A8 (oc), 10 GND (power) hidden to GND, 11 B8 (in), 12 B7 (in), 13 B6 (in), 14 B5 (in), 15 B4 (in), 16 B3 (in), 17 B2 (in), 18 B1 (in), 19 ~{G}BA (in), 20 VCC (power) hidden to VCC
1 alternate drawing of the same symbol

## SN74LS623
designator U?
OCTAL BUS TRANCEIVER
footprint SO20W
footprint DIP-20
pins: 1 GAB (in), 2 A1 (hiz), 3 A2 (hiz), 4 A3 (hiz), 5 A4 (hiz), 6 A5 (hiz), 7 A6 (hiz), 8 A7 (hiz), 9 A8 (hiz), 10 GND (power) hidden to GND, 11 B8 (in), 12 B7 (in), 13 B6 (in), 14 B5 (in), 15 B4 (in), 16 B3 (in), 17 B2 (in), 18 B1 (in), 19 ~{G}BA (in), 20 VCC (power) hidden to VCC
1 alternate drawing of the same symbol

## SN74LS624
designator U?
VOLTAGE-CONTROLLED OSC
footprint DIP-14
footprint SO14
pins: 1 OSC GND (power), 2 RNG, 3 CX1, 4 CX2, 5 ~{EN} (in), 6 Y (out), 7 GND (power) hidden to GND, 8 Z (out), 9 VCC (power) hidden to VCC, 13 FC, 14 OSC VCC (power)
1 alternate drawing of the same symbol

## SN74LS625
designator U?
VOLTAGE-CONTROLLED OSC
footprint DIP-16
footprint SO16
part A pins: 1 GND (power) hidden to GND, 2 Z (out), 3 Y (out), 4 CX1, 5 CX2, 6 FC, 7 OSC VCC (power), 8 OSC GND (power), 16 VCC (power) hidden to VCC
part B pins: 1 GND (power) hidden to GND, 9 OSC GND (power), 10 OSC VCC (power), 11 FC, 12 CX2, 13 CX1, 14 Y (out), 15 Z (out), 16 VCC (power) hidden to VCC
1 alternate drawing of the same symbol

## SN74LS626
designator U?
VOLTAGE-CONTROLLED OSC
footprint DIP-16
footprint SO16
pins: 1 GND (power) hidden to GND, 2 1Z (out), 3 1Y (out), 4 1~{EN} (in), 5 1CX1, 6 1CX2, 7 OSC VCC (power), 8 OSC GND (power), 9 1FC, 10 2FC, 11 2CX2, 12 2CX1, 13 2~{EN} (in), 14 2Y (out), 15 2Z (out), 16 VCC (power) hidden to VCC
1 alternate drawing of the same symbol

## SN74LS627
designator U?
VOLTAGE-CONTROLLED OSC
footprint SO14
footprint DIP-14
part A pins: 1 OSC VCC (power), 2 FC, 3 CX1, 4 CX2, 5 OSC GND (power), 6 Y (out), 7 GND (power) hidden to GND, 14 VCC (power) hidden to VCC
part B pins: 7 GND (power) hidden to GND, 8 Y (out), 9 OSC GND (power), 10 CX2, 11 CX1, 12 FC, 13 OSC VCC (power), 14 VCC (power) hidden to VCC
1 alternate drawing of the same symbol

## SN74LS628
designator U?
VOLTAGE-CONTROLLED OSC
footprint DIP-14
footprint SO14
pins: 1 OSC GND (power), 2 RNG, 3 CX1, 4 CX2, 5 ~{EN} (in), 6 Y (out), 7 GND (power) hidden to GND, 8 Z (out), 9 VCC (power) hidden to VCC, 11 RX, 12 RX, 13 FC, 14 OSC VCC (power)
1 alternate drawing of the same symbol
